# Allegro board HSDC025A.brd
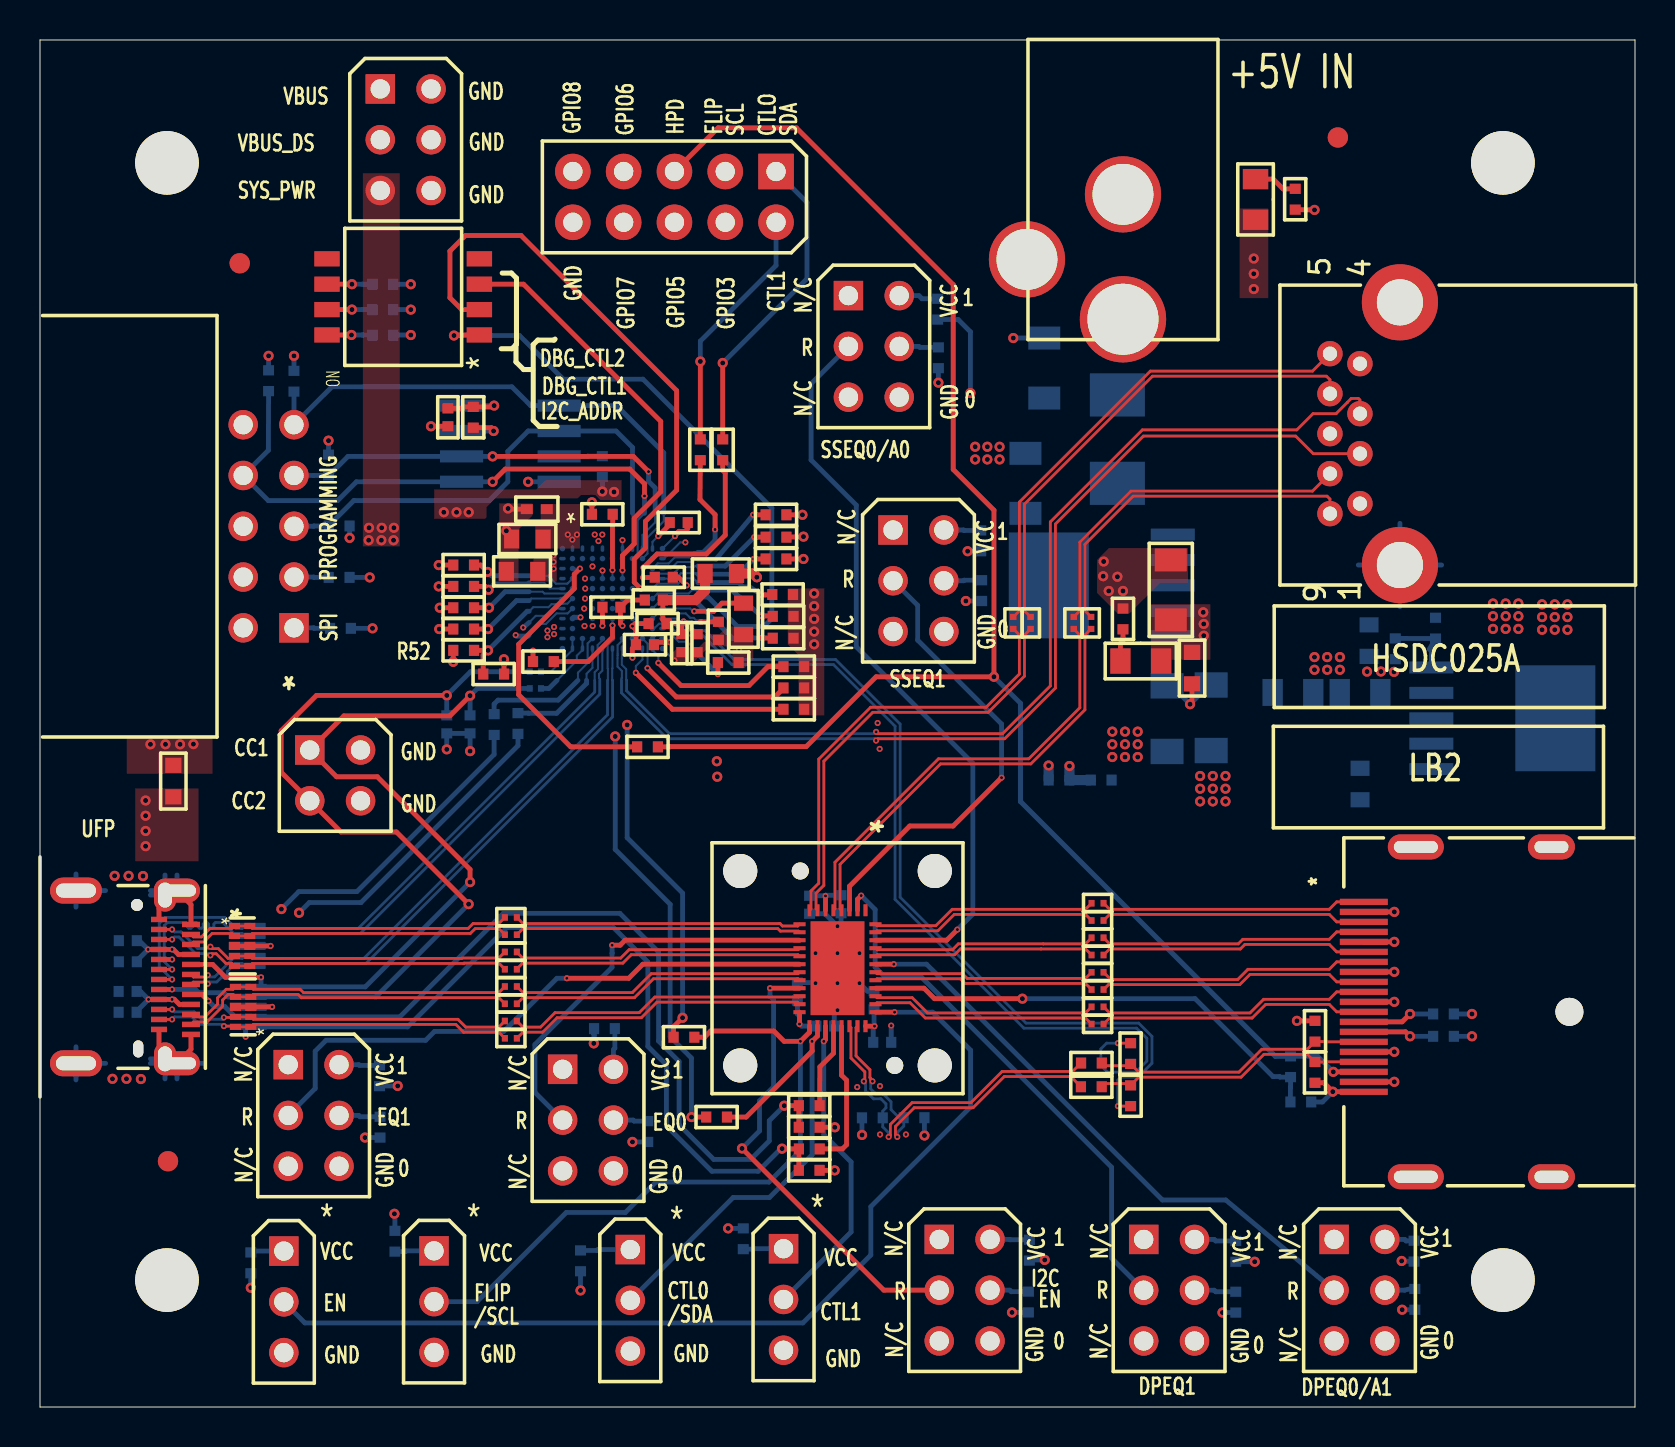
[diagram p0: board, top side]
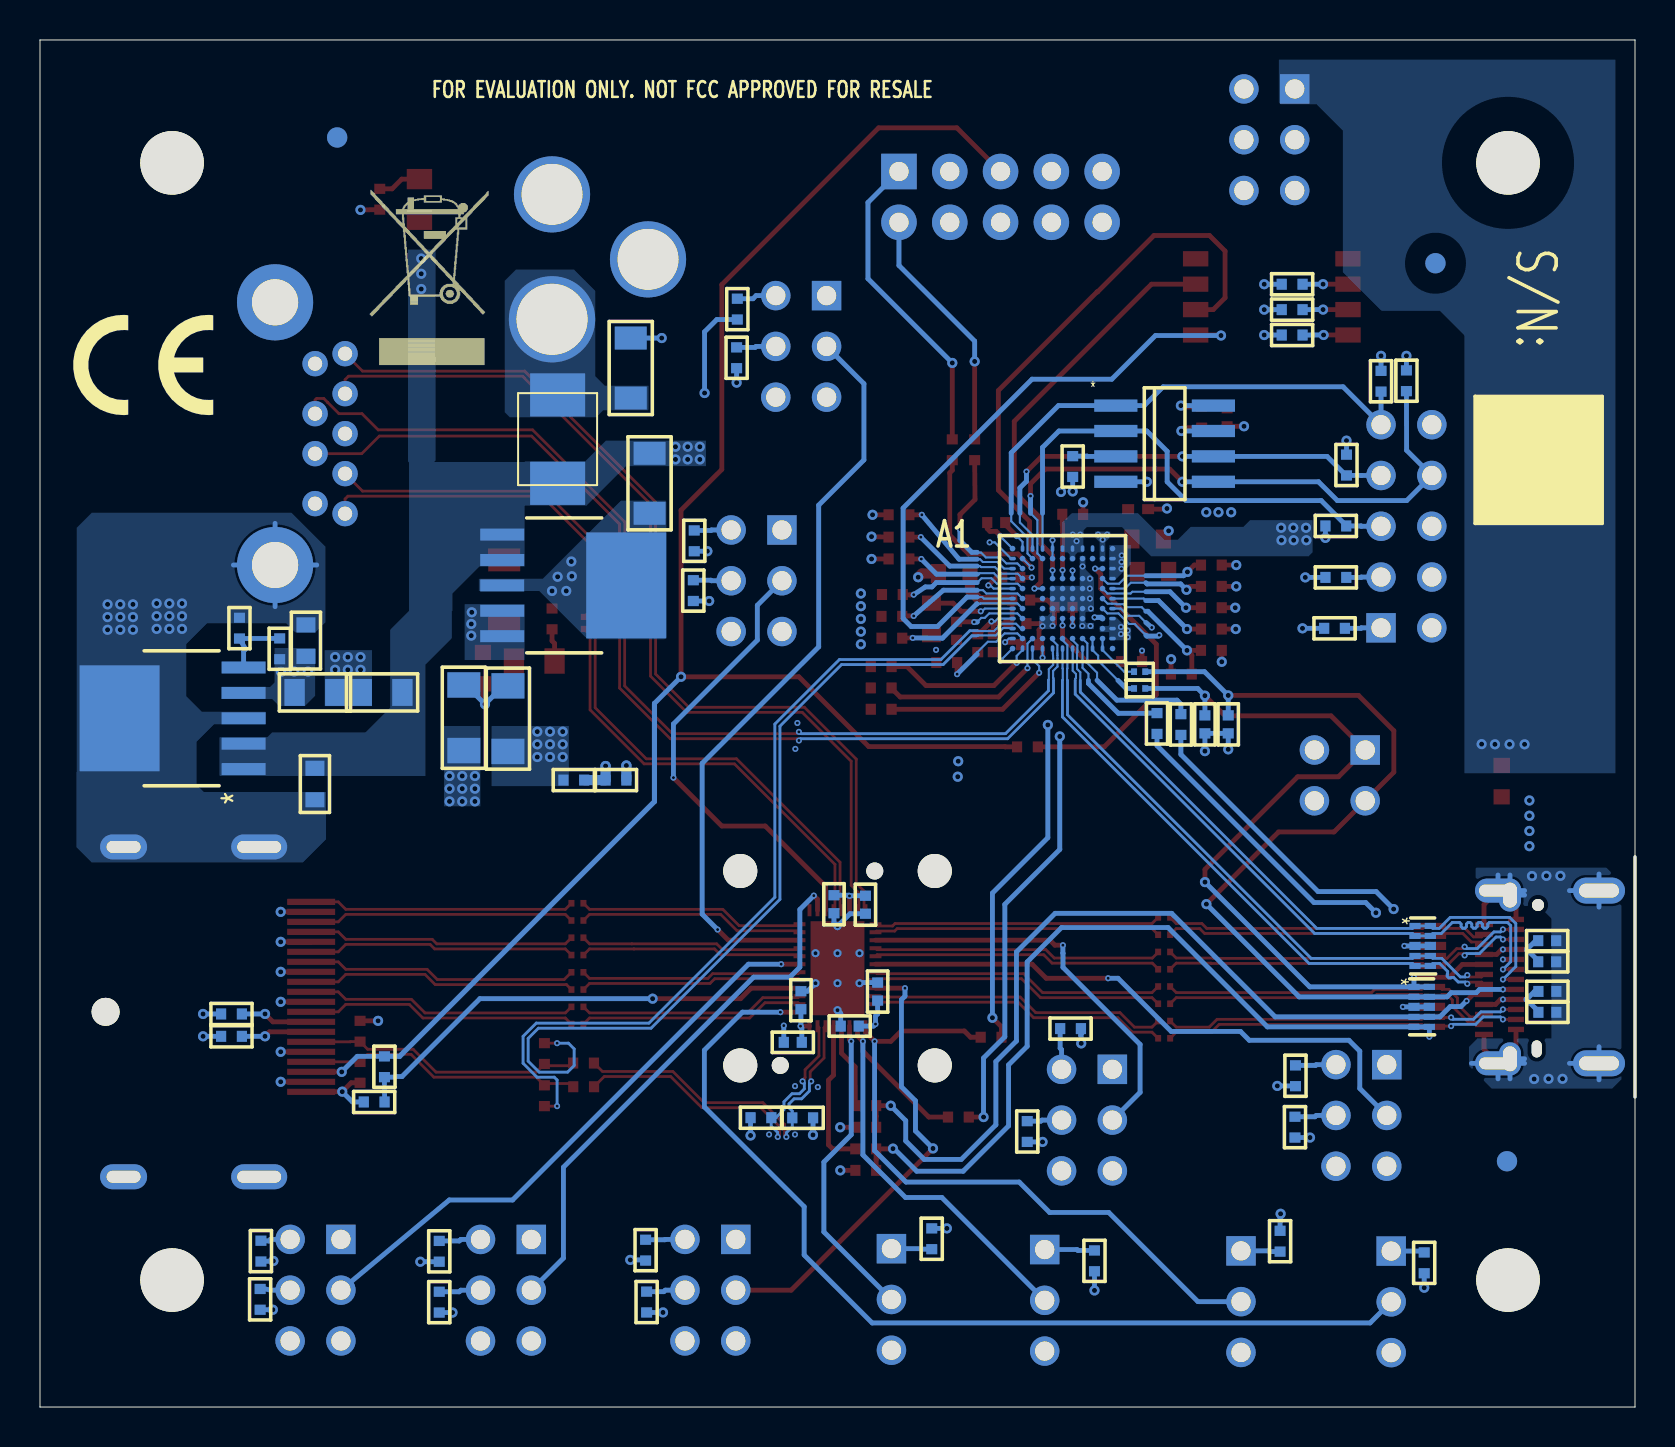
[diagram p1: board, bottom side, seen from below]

Outline 79.76 x 68.38 mm; copper layers: TOP, L2_GND, L3_PWR, L4_PWR, L5_GND, BOTTOM. Coordinates in mm from the lower left corner of the outline.
Outline path: 0,68.38 79.76,68.38 79.76,0 0,0 0,68.38

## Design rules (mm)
net group DIFFPAIR0: nets SSTXN SSTXP
net group DIFFPAIR1: nets SSRXN SSRXP
net group DIFFPAIR2: nets N73513 N73520
net group DIFFPAIR3: nets N53113 N53117
net group DIFFPAIR4: nets USB_N USB_P
net group DIFFPAIR5: nets RX1N RX1P
net group DIFFPAIR6: nets C_USB_BN C_USB_BP
net group DIFFPAIR7: nets TX2N TX2P
net group DIFFPAIR8: nets RX2N RX2P
net group DIFFPAIR9: nets C_USB_TN C_USB_TP
net group DIFFPAIR10: nets TX1N TX1P
net group DIFFPAIR11: nets DP0N DP0P
net group DIFFPAIR12: nets DP1N DP1P
net group DIFFPAIR13: nets DP2N DP2P
net group DIFFPAIR14: nets DP3N DP3P
net group DIFFPAIR15: nets AUXN AUXP
net group DIFFPAIR16: nets N53375 N53379
net group DIFFPAIR17: nets N53383 N53387
net group DIFFPAIR18: nets N53391 N53395
net group DIFFPAIR19: nets N53399 N53403
net group DIFFPAIR20: nets N62024 N62031
net group DIFFPAIR21: nets N52896 N52900
net group DIFFPAIR22: nets N16705873 N16705894
net group DIFFPAIR23: nets N16705898 N16705902
net group DIFFPAIR24: nets N52912 N52916
net group DIFFPAIR25: nets TPS_AUX_N TPS_AUX_P

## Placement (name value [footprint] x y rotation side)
C1  100nF  [C0201]  49.53 39.22 270 top
C2  470nF  [C0201]  51.69 39.22 90 top
C3  470nF  [C0201]  52.55 39.22 90 top
C4  220nF  [C0201]  23.55 24.49 0 top
C5  100nF  [C0201]  52.88 25.2 0 top
C6  220nF  [C0201]  23.55 23.62 0 top
C7  100nF  [C0201]  52.88 24.33 0 top
C8  470nF  [C0201]  23.55 22.76 0 top
C9  100nF  [C0201]  48.67 39.22 270 top
C10  100nF  [C0201]  52.88 23.47 0 top
C11  470nF  [C0201]  23.55 21.9 0 top
C12  100nF  [C0201]  52.88 22.61 0 top
C13  470nF  [C0201]  23.55 21.03 0 top
C14  100nF  [C0201]  52.88 21.74 0 top
C15  470nF  [C0201]  23.55 20.17 0 top
C16  100nF  [C0201]  52.88 20.88 0 top
C17  220nF  [C0201]  23.55 19.31 0 top
C18  100nF  [C0201]  52.88 20.02 0 top
C19  220nF  [C0201]  23.55 18.44 0 top
C20  100nF  [C0201]  52.88 19.15 0 top
C21  1uF  [C0402]  38.48 25.12 270 bottom
C22  1uF  [C0402]  41.71 20.35 90 bottom
C23  1uF  [C0402]  42.11 18.24 0 bottom
C24  100nF  [C0402]  40.06 25.15 270 bottom
C25  100nF  [C0402]  37.87 20.78 90 bottom
C26  10nF  [C0402]  39.27 19.05 0 bottom
C27  0.22uF  [C0402]  28.57 40.01 0 top
C28  330pF  [C0402]  21.51 34.15 270 bottom
C29  330pF  [C0402]  20.34 34.15 270 bottom
C30  10uF  [C0603]  35.18 39.42 270 top
C31  1uF  [C0402]  31.94 44.24 0 top
C32  1uF  [C0402]  30.25 38.13 180 top
C33  1uF  [C0402]  31.19 41.5 180 top
C34  1uF  [C0402]  33.92 38.82 270 top
C35  1uF  [C0402]  30.69 40.36 180 top
C36  1uF  [C0402]  32.09 38.21 270 top
C37  0.1uF  [C0402]  30.88 39.18 180 top
C38  0.1uF  [C0402]  32.87 38.2 270 top
C39  0.01uF  [C0402]  20.4 49.5 270 top
C40  22uF  [C1206]  49.28 46.2 270 bottom
C41  10uF  [C1206]  56.54 40.87 90 top
C42  10uF  [C1206]  50.22 51.97 90 bottom
C43  10uF  [C0603]  66.46 38.33 90 bottom
C44  10uF  [C0603]  66.01 31.16 270 bottom
C45  10nF  [C0402]  4.38 20.79 180 bottom
C46  10nF  [C0402]  4.38 19.74 180 bottom
C47  10nF  [C0402]  4.39 23.32 180 bottom
C48  10nF  [C0402]  4.39 22.27 180 bottom
C49  10uF  [C0603]  24.1 41.8 180 top
C50  10uF  [C0603]  34.04 41.69 0 top
C51  1uF 25V  [C0603]  24.37 43.42 180 top
D1  SCHOTTKY  [DO-214AA]  53.87 48.41 90 bottom
D2  LED Green  [0805]  55.04 37.31 180 top
D3  TPD1E10B06  [DPY0002AA]  24.84 44.91 180 top
D4  LED Green 0805  [0805]  60.78 60.4 90 top
FB1  26 @ 100MHZ  [0603]  57.61 36.96 90 top
FB2  26 @ 100MHZ  [0603]  6.67 31.31 90 top
J1  HDR3X1 M .1  [HDR_THVT_1X3_100_M]  19.7 7.81 0 top
J2  HDR3X1 M .1  [HDR_THVT_1X3_100_M]  29.52 7.88 0 top
J3  HDR3X1 M .1  [HDR_THVT_1X3_100_M]  37.18 7.92 0 top
J4  HDR3X1 M .1  [HDR_THVT_1X3_100_M]  12.19 7.8 0 top
J5  HDR3X2 .1X.1  [HDR_THVT_2X3_100_M]  17.02 65.93 0 top
J6  HDR2X2 M .1X.1  [HDR_THVT_2X2_100]  13.49 32.86 0 top
J7  Header 5x2 0.1" Shroud RA thru-hole  [HDR_THRT_2X5_100]  12.7 38.97 180 top
J8  2.1mm x 5.5mm  [PJ-202AH]  54.15 54.41 180 top
JMP1  HDR3X2 .1X.1  [HDR_THVT_2X3_100_M]  12.41 17.12 0 top
JMP2  HDR3X2 .1X.1  [HDR_THVT_2X3_100_M]  26.13 16.89 0 top
JMP3  HDR3X2 .1X.1  [HDR_THVT_2X3_100_M]  42.66 43.87 0 top
JMP4  HDR3X2 .1X.1  [HDR_THVT_2X3_100_M]  40.42 55.59 0 top
JMP5  HDR3X2 .1X.1  [HDR_THVT_2X3_100_M]  55.19 8.38 0 top
JMP6  HDR3X2 .1X.1  [HDR_THVT_2X3_100_M]  64.71 8.38 0 top
JMP7  HDR3X2 .1X.1  [HDR_THVT_2X3_100_M]  44.97 8.38 0 top
JMP8  Header 5x2  [HDR_THVT_2X5_100]  36.8 61.8 270 top
NOREF  -  []  79.76 0 90 top
NOREF#2  -  []  0 68.38 0 top
NOREF#3  -  []  0 0 0 top
NOREF#4  -  [unnamed#2]  6.35 6.35 0 top
NOREF#5  -  []  88.9 38.1 0 top
NOREF#6  -  [unnamed#2]  73.15 62.23 0 top
NOREF#7  -  [unnamed#2]  73.15 6.35 0 top
NOREF#8  -  [unnamed#2]  6.4 12.29 0 top
NOREF#9  -  [unnamed#2]  64.9 63.5 0 top
NOREF#10  -  []  -3.81 -69.85 0 top
NOREF#11  -  [unnamed#2]  9.99 57.21 0 top
NOREF#12  -  [unnamed#2]  6.35 62.23 0 top
NOREF#13  -  []  40.28 58.8 0 top
NOREF#14  -  []  60.26 57.7 180 bottom
NOREF#15  -  [unnamed#2]  64.9 63.5 180 bottom
NOREF#16  -  [unnamed#2]  6.4 12.29 180 bottom
NOREF#17  -  []  74.59 52.12 180 bottom
NOREF#18  -  []  7 32.26 180 bottom
NOREF#19  -  [unnamed#2]  9.98 57.21 180 bottom
NOREF#20  -  []  4.82 57.53 270 bottom
P1  JAE  DX07S024JJ2  [USB-C_SMRT_DX07S024JJ2]  4.85 21.51 270 top
P2  USB3 Type A Receptacle  [USB3_TYPEA]  64.5 48.69 90 top
P3  Display_Port_Connector_Source  [CON_DP_SD-47272-001]  76.48 19.77 90 top
R1  10k DNI  [R0402]  63.05 15.26 180 bottom
R2  0  [R0402]  62.53 17.02 90 bottom
R3  0 DNI  [R0402]  32.2 18.5 0 top
R4  100k DNI  [R0402]  63.75 16.74 90 top
R5  0 DNI  [R0402]  33.83 14.5 0 top
R6  0  [R0402]  52.57 16.02 0 top
R7  0  [R0402]  38.47 15.07 0 top
R8  0  [R0402]  52.58 17.21 0 top
R9  1M  [R0402]  70.18 19.66 0 bottom
R10  5M  [R0402]  70.18 18.54 0 bottom
R11  0  [R0402]  38.47 12.91 0 top
R12  1M DNI  [R0402]  41.62 14.47 180 bottom
R13  1M DNI  [R0402]  43.71 14.47 0 bottom
R14  100k DNI  [R0402]  63.75 18.8 90 top
R15  0 DNI  [R0402]  22.71 34.14 90 bottom
R16  0 DNI  [R0402]  23.9 34.19 90 bottom
R17  0 DNI  [R0402]  54.53 17.68 90 top
R18  0 DNI  [R0402]  54.53 15.57 270 top
R19  1K  [R0402]  16.98 16.57 270 bottom
R20  1K  [R0402]  28.22 18.93 180 bottom
R21  20K  [R0402]  17 14 270 bottom
R22  1K  [R0402]  17.75 8.29 90 bottom
R23  20K  [R0402]  30.39 13.78 270 bottom
R24  1K  [R0402]  47.04 43.32 270 bottom
R25  1K  [R0402]  44.89 54.91 270 bottom
R26  20K  [R0402]  47.09 40.84 270 bottom
R27  20K  [R0402]  44.92 52.48 270 bottom
R28  1K  [R0402]  27.03 7.31 270 bottom
R29  1K  [R0402]  59.79 7.79 270 bottom
R30  1K  [R0402]  68.71 7.8 270 bottom
R31  20K  [R0402]  59.79 5.25 270 bottom
R32  20K  [R0402]  68.75 5.38 270 bottom
R33  1K  [R0402]  35.17 8.42 90 bottom
R34  1K  [R0402]  49.47 7.85 270 bottom
R35  1K  [R0402]  10.54 7.21 270 bottom
R36  20K  [R0402]  49.42 5.25 270 bottom
R37  0  [R0201]  24.77 35.94 180 bottom
R38  0  [R0201]  24.77 36.78 180 bottom
R39  15k 0.1%  [R0402]  37.16 38.46 0 top
R40  0  [R0402]  30.38 33.02 180 top
R41  0  [R0402]  34.14 47.88 90 top
R42  0  [R0402]  21.18 39.98 0 top
R43  0  [R0402]  33.02 47.88 90 top
R44  0  [R0402]  21.18 42.11 180 top
R45  1M  [R0402]  37.69 37.03 180 top
R46  0 DNI  [R0402]  25.17 37.29 180 top
R47  1M  [R0402]  34.42 37.24 180 top
R48  1M  [R0402]  37.69 34.9 180 top
R49  1M  [R0402]  37.69 35.97 180 top
R50  1M  [R0402]  21.18 41.05 180 top
R51  1M  [R0402]  21.18 38.91 180 top
R52  100k DNI  [R0402]  21.18 37.85 180 top
R53  100k  [R0402]  37.13 40.64 180 top
R57  10k  [R0402]  36.8 44.63 180 top
R58  3.3k  [R0402]  36.8 43.51 180 top
R59  3.3k  [R0402]  36.8 42.42 180 top
R60  100k  [R0402]  37.16 39.55 180 top
R61  1K  [R0402]  28.12 44.65 180 top
R62  1K  [R0402]  17.14 56.16 0 bottom
R63  1K  [R0402]  17.14 54.89 0 bottom
R64  1K  [R0402]  17.14 53.62 0 bottom
R66  0  [R0402]  15.02 38.95 180 bottom
R67  3.3k  [R0402]  12.7 51.31 270 bottom
R68  3.3k  [R0402]  14.96 44.07 180 bottom
R70  0  [R0402]  14.96 41.5 180 bottom
R71  3.3k DNI  [R0402]  11.43 51.33 270 bottom
R72  3.3k  [R0402]  14.43 47.12 270 bottom
R73  3.3k  [R0402]  28.12 47.04 270 bottom
R74  3.3k  [R0402]  21.67 49.5 270 top
R75  0  [R1206]  58.56 34.48 90 bottom
R76  0  [R1206]  56.36 34.43 90 bottom
R77  330  [R0402]  54.15 39.42 90 top
R78  330  [R0402]  62.77 60.41 270 top
R79  0 DNI  [R0805]  66.01 35.74 180 bottom
R80  3.9K  [R0402]  67.77 37.92 90 bottom
R81  1.2K  [R0402]  69.78 38.96 90 bottom
R82  0 DNI  [R0805]  62.65 35.74 180 bottom
R83  2M  [R0402]  38.46 13.99 0 top
R84  2M  [R0402]  38.46 11.84 0 top
R85  0  [R0402]  53.06 31.36 180 bottom
R86  0 DNI  [R0402]  50.95 31.36 180 bottom
R87  100k  [R0402]  22.68 36.66 0 top
SW1  4-POS 50-MIL SMT  [SW_SMVT_DIP_4POS_8]  18.16 55.53 90 top
U1  TUSB1064  [SKT_IRONWOOD_C14861_QFN-40]  39.88 21.95 270 top
U2  TPD4E05U06  [DQA]  10.11 23.06 270 top
U3  TPD4E05U06  [DQA]  10.67 20.02 270 bottom
U4  TPD4E05U06  [DQA]  10.16 20.02 90 top
U5  TPD4E05U06  [DQA]  10.62 23.06 270 bottom
U6  TPS65986  [ZQZ_BGA_96]  28.63 40.44 180 bottom
U7  W25Q80  [SOIC_8_197X157_50]  23.52 48.18 180 bottom
U8  TPS7A4533  [DCQ_PDSO_6]  53.54 41.1 270 bottom
U9  TPS7A4501  [DCQ_PDSO_6]  72.67 34.45 90 bottom

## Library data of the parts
C1-C20 = cc0201
C21-C29 C31-C39 C45-C48 = cc0402
C30 C43 C44 C49-C51 = cc0603
C40-C42 = CAP NP
D1 = SCHOTTKY_2
D2 D4 = DIODE
D3 = TPD1E10B06
FB1 FB2 = FERRITE BEAD
J1-J4 = HDR3X1 M .1
J5 JMP1-JMP7 = HDR3X2 M .1X.1
J6 = HDR2X2 M .1X.1
J7 = CONN PCB 5x2-S
J8 = BNC_2
JMP8 = Header 5x2
P1 = TypeC_JAE_TopMNT_0
P2 = USB 3.0 Type A Receptacle
P3 = Display_Port_Connector_Source
R1-R36 R39-R53 R57-R64 R66-R68 R70-R74 R80 R81 R83-R87 = r0402
R37 R38 = r0201
R75 R76 = r1206
R77 R78 = R
R79 R82 = r0805
SW1 = SW DIP-4
U1 = TUSB1064
U2-U5 = TPD4E05U06
U6 = TPS65982_0
U7 = W25Q80SSI
U8 = TPS79633KTT_2
U9 = TPS7A4501

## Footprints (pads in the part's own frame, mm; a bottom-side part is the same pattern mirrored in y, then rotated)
0603
  rect 0.762x0.813 smd: 1(-0.787,0) 2(0.787,0)
0805
  rect 1.016x1.27 smd: 1(-1.016,0) 2(1.016,0)
C0201
  rect 0.3x0.33 smd: 1(-0.3,0) 2(0.3,0)
C0402
  rect 0.51x0.55 smd: 1(-0.45,0) 2(0.45,0)
C0603
  rect 0.76x0.95 smd: 1(-0.787,0) 2(0.787,0)
C1206
  rect 1.15x1.6 smd: 1(-1.5,0) 2(1.5,0)
CON_DP_SD-47272-001
  round 1.4 hole 1.4 unplated: (0,0)
  rect 0.31x2.4 smd: 1(5.5,10.28) 2(5,10.28) 3(4.5,10.28) 4(4,10.28) 5(3.5,10.28) 6(3,10.28) 7(2.5,10.28) 8(2,10.28) 9(1.5,10.28) 10(1,10.28) 11(0.5,10.28) 12(0,10.28) 13(-0.5,10.28) 14(-1,10.28) 15(-1.5,10.28) 16(-2,10.28) 17(-2.5,10.28) 18(-3,10.28) 19(-3.5,10.28) 20(-4,10.28)
  oval 1.25x2.8 hole 0.6x2.2: 21(-8.25,7.68) 24(8.25,7.68)
  oval 1.25x2.35 hole 0.6x1.7: 22(-8.25,0.9) 23(8.25,0.9)
DCQ_PDSO_6
  rect 0.6x2.2 smd: 1(-2.54,-3.1) 2(-1.27,-3.1) 3(0,-3.1) 4(1.27,-3.1) 5(2.54,-3.1)
  rect 5.3x4 smd: 6(0,3.1)
DO-214AA
  rect 2.16x2.75 smd: 1(-2.21,0) 2(2.21,0)
DPY0002AA
  rect 0.6x0.5 smd: 1(-0.5,0) 2(0.5,0)
DQA
  rect 0.305x0.559 smd: 1(-1,-0.385) 2(-0.5,-0.385) 4(0.5,-0.385) 5(1,-0.385) 6(1,0.385) 7(0.5,0.385) 9(-0.5,0.385) 10(-1,0.385)
  rect 0.406x0.559 smd: 3(0,-0.385) 8(0,0.385)
HDR_THRT_2X5_100
  rect 1.473x1.473 hole 0.965: 1(0,0)
  round 1.473 hole 0.965: 2(2.54,0) 3(0,-2.54) 4(2.54,-2.54) 5(0,-5.08) 6(2.54,-5.08) 7(0,-7.62) 8(2.54,-7.62) 9(0,-10.16) 10(2.54,-10.16)
HDR_THVT_1X3_100_M
  rect 1.473x1.473 hole 0.965: 1(0,0)
  round 1.473 hole 0.965: 2(0,-2.54) 3(0,-5.08)
HDR_THVT_2X2_100
  rect 1.473x1.473 hole 0.965: 1(0,0)
  round 1.473 hole 0.965: 2(2.54,0) 3(0,-2.54) 4(2.54,-2.54)
HDR_THVT_2X3_100_M
  rect 1.473x1.473 hole 0.965: 1(0,0)
  round 1.473 hole 0.965: 2(2.54,0) 3(0,-2.54) 4(2.54,-2.54) 5(0,-5.08) 6(2.54,-5.08)
HDR_THVT_2X5_100
  rect 1.778x1.778 hole 0.965: 1(0,0)
  round 1.778 hole 0.965: 2(2.54,0) 3(0,-2.54) 4(2.54,-2.54) 5(0,-5.08) 6(2.54,-5.08) 7(0,-7.62) 8(2.54,-7.62) 9(0,-10.16) 10(2.54,-10.16)
PJ-202AH
  round 4.318 hole 3.556: 1(0,0)
  round 3.81 hole 3.048: 2(4.801,-2.997) 3(0,-6.248)
R0201
  rect 0.3x0.33 smd: 1(-0.285,0) 2(0.275,0)
R0402
  rect 0.51x0.55 smd: 1(-0.52,0) 2(0.52,0)
R0805
  rect 1.02x1.35 smd: 1(-1.016,0) 2(1.016,0)
R1206
  rect 1.27x1.65 smd: 1(-1.64,0) 2(1.64,0)
SKT_IRONWOOD_C14861_QFN-40
  round 1.702 hole 1.702 unplated: (-4.863,4.863) (-4.863,-4.863) (4.863,4.863) (4.863,-4.863)
  round 0.85 hole 0.85 unplated: (-4.863,-1.863) (4.863,2.863)
  rect 0.6x0.2 smd: 1(-2.9,1.4) 2(-2.9,1) 3(-2.9,0.6) 4(-2.9,0.2) 5(-2.9,-0.2) 6(-2.9,-0.6) 7(-2.9,-1) 8(-2.9,-1.4) 21(2.9,-1.4) 22(2.9,-1) 23(2.9,-0.6) 24(2.9,-0.2) 25(2.9,0.2) 26(2.9,0.6) 27(2.9,1) 28(2.9,1.4)
  rect 0.2x0.6 smd: 9(-2.2,-1.9) 10(-1.8,-1.9) 11(-1.4,-1.9) 12(-1,-1.9) 13(-0.6,-1.9) 14(-0.2,-1.9) 15(0.2,-1.9) 16(0.6,-1.9) 17(1,-1.9) 18(1.4,-1.9) 19(1.8,-1.9) 20(2.2,-1.9) 29(2.2,1.9) 30(1.8,1.9) 31(1.4,1.9) 32(1,1.9) 33(0.6,1.9) 34(0.2,1.9) 35(-0.2,1.9) 36(-0.6,1.9) 37(-1,1.9) 38(-1.4,1.9) 39(-1.8,1.9) 40(-2.2,1.9)
  rect 4.699x2.692 smd: 41(0,0)
SOIC_8_197X157_50
  rect 2.159x0.61 smd: 1(-2.44,1.905) 2(-2.44,0.635) 3(-2.44,-0.635) 4(-2.44,-1.905) 5(2.44,-1.905) 6(2.44,-0.635) 7(2.44,0.635) 8(2.44,1.905)
SW_SMVT_DIP_4POS_8
  rect 0.762x1.27 smd: 1(-1.905,-3.81) 2(-0.635,-3.81) 3(0.635,-3.81) 4(1.905,-3.81) 5(1.905,3.81) 6(0.635,3.81) 7(-0.635,3.81) 8(-1.905,3.81)
unnamed#2
  round 3.175 hole 3.175 unplated: (0,0)
USB3_TYPEA
  round 1.27 hole 0.711: 1(-3.5,-1.5) 2(-1,-1.5) 3(1,-1.5) 4(3.5,-1.5) 5(4,0) 6(2,0) 7(0,0) 8(-2,0) 9(-4,0)
  round 3.81 hole 2.311: 10(-6.57,-3.5) 11(6.57,-3.5)
USB-C_SMRT_DX07S024JJ2
  round 0.6 hole 0.6 unplated: (-3.6,0)
  oval 0.85x0.5 hole 0.85x0.5 unplated: (3.6,0.065)
  oval 1.65x1.1 hole 1.25x0.7: 1(-4.095,1.4) 5(4.095,1.4)
  oval 1.2x2.3 hole 0.6x1.9: 2(-4.32,2) 6(4.32,2)
  oval 1.3x2.6 hole 0.7x2: 3(-4.32,-3.05) 4(4.32,-3.05)
  rect 0.27x0.9 smd: A1(-2.625,2.7) A2(-2.125,2.7) A3(-1.625,2.7) A4(-1.125,2.7) A5(-0.625,2.7) A6(-0.125,2.7) A7(0.375,2.7) A8(0.875,2.7) A9(1.375,2.7) A10(1.875,2.7) A11(2.375,2.7) A12(2.875,2.7)
  rect 0.27x0.8 smd: B1(2.625,1.1) B2(2.125,1.1) B3(1.625,1.1) B4(1.125,1.1) B5(0.625,1.1) B6(0.125,1.1) B7(-0.375,1.1) B8(-0.875,1.1) B9(-1.375,1.1) B10(-1.875,1.1) B11(-2.375,1.1) B12(-2.875,1.1)
ZQZ_BGA_96
  round 0.28 smd: A1(-2.5,2.5) A11(2.5,2.5) B2(-2,2) B3(-1.5,2) B4(-1,2) B5(-0.5,2) B6(0,2) B7(0.5,2) B8(1,2) B9(1.5,2) B10(2,2) C2(-2,1.5) C10(2,1.5) D2(-2,1) D5(-0.5,1) D6(0,1) D7(0.5,1) D8(1,1) D10(2,1) E2(-2,0.5) E4(-1,0.5) E5(-0.5,0.5) E6(0,0.5) E7(0.5,0.5) E8(1,0.5) E10(2,0.5) F2(-2,0) F4(-1,0) F5(-0.5,0) F6(0,0) F7(0.5,0) F8(1,0) F10(2,0) G2(-2,-0.5) G4(-1,-0.5) G5(-0.5,-0.5) G6(0,-0.5) G7(0.5,-0.5) G8(1,-0.5) G10(2,-0.5) H2(-2,-1) H4(-1,-1) H5(-0.5,-1) H6(0,-1) H7(0.5,-1) H8(1,-1) H10(2,-1) J2(-2,-1.5) J10(2,-1.5) K2(-2,-2) K3(-1.5,-2) K4(-1,-2) K5(-0.5,-2) K6(0,-2) K7(0.5,-2) K8(1,-2) K9(1.5,-2) K10(2,-2) L1(-2.5,-2.5) L11(2.5,-2.5)
  oval 0.18x0.33 smd: A2(-2,2.5) A3(-1.5,2.5) A4(-1,2.5) A5(-0.5,2.5) A6(0,2.5) A7(0.5,2.5) A8(1,2.5) A9(1.5,2.5) A10(2,2.5) L2(-2,-2.5) L3(-1.5,-2.5) L4(-1,-2.5) L5(-0.5,-2.5) L6(0,-2.5) L7(0.5,-2.5) L8(1,-2.5) L9(1.5,-2.5) L10(2,-2.5)
  oval 0.33x0.18 smd: B1(-2.5,2) B11(2.5,2) C1(-2.5,1.5) C11(2.5,1.5) D1(-2.5,1) D11(2.5,1) E1(-2.5,0.5) E11(2.5,0.5) F1(-2.5,0) F11(2.5,0) G1(-2.5,-0.5) G11(2.5,-0.5) H1(-2.5,-1) H11(2.5,-1) J1(-2.5,-1.5) J11(2.5,-1.5) K1(-2.5,-2) K11(2.5,-2)

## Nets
GND: C21.2 C22.2 C23.2 C24.2 C25.2 C26.2 C27.2 C28.2 C29.2 C30.2 C31.2 C32.2 C33.2 C34.2 C35.2 C36.2 C37.2 C38.2 C39.2 C40.2 C41.2 C42.2 C43.2 C44.2 C45.2 C46.2 C47.2 C48.2 C49.2 C50.2 C51.2 D3.2 J1.3 J2.3 J3.3 J4.3 J5.2 J5.4 J5.6 J6.2 J6.4 J7.2(6) J7.10 J8.2(S) J8.3(SW) JMP1.6 JMP2.6 JMP3.6 JMP4.6 JMP5.6 JMP6.6 JMP7.6 JMP8.10 P1.1(CHASSIS#1) P1.2(CHASSIS#2) P1.3(CHASSIS#3) P1.4(CHASSIS#4) P1.5(CHASSIS#5) P1.6(CHASSIS#6) P1.A1(GND#A1) P1.A12(GND#A12) P1.B1(GND#B1) P1.B12(GND#B12) P2.4(GND) P2.7(GND_DRAIN) P2.10(SHIELD1) P2.11(SHIELD2) P3.2(GND1) P3.5(GND2) P3.8(GND3) P3.11(GND4) P3.16(GND6) P3.19(RTN) P3.21(GND7) P3.22(GND8) P3.23(GND9) P3.24(GND10) R9.2 R10.2 R13.2 R14.2 R21.2 R23.2 R26.2 R27.2 R31.2 R32.2 R36.2 R39.2 R45.1 R47.1 R48.1 R49.1 R50.2 R51.2 R53.1 R60.1 R61.2 R62.2 R63.2 R64.2 R77.2 R78.2 R81.2 R83.2 R84.2 U1.41(PAD/GND) U2.3(GND#3) U2.8(GND#8) U3.3(GND#3) U3.8(GND#8) U4.3(GND#3) U4.8(GND#8) U5.3(GND#3) U5.8(GND#8) U6.A1(GND#A1) U6.A5(GND#A5) U6.B5(GND#B5) U6.B8(GND#B8) U6.D8(GND#D8) U6.E5(GND#E5) U6.E6(GND#E6) U6.E7(GND#E7) U6.E8(GND#E8) U6.F5(GND#F5) U6.F6(GND#F6) U6.F7(GND#F7) U6.F8(GND#F8) U6.G5(GND#G5) U6.G6(GND#G6) U6.G7(GND#G7) U6.G8(GND#G8) U6.H4(GND#H4) U6.H5(GND#H5) U6.H8(GND#H8) U6.L1(GND#L1) U6.L4(GND#L4) U7.4(GND) U8.3(GND#3) U8.6(GND#6) U9.3(GND#3) U9.6(GND#6)
VBUS: C51.1 D3.1 FB2.2 J5.1 R79.2 R82.1 U6.A10(SENSEN) U6.B10(SENSEP) U6.H11(VBUS1) U6.J10(VBUS2) U6.J11(VBUS3) U6.K11(VBUS4)
VBUS_DS: C43.1 C49.1 J5.3 P2.1(VBUS) R79.1 R80.1 U6.A11(PP_5V0_2) U6.B11(PP_5V0_1) U6.C11(PP_5V0_3) U6.D11(PP_5V0_4) U6.H10(PP_CABLE) U9.4(OUT)
VDDIO: R85.2 R86.1 U6.B1(VDDIO)
3P3VCC: C41.1 D2.1(A) FB1.2 P3.20(DP_PWR) R1.1 R4.1 R12.2 U8.4(OUT) U8.5(SENSE)
1064_VCC: C21.1 C22.1 C23.1 C24.1 C25.1 C26.1 R19.2 R20.2 R22.2 R24.2 R25.2 R28.2 R29.2 R30.2 R33.2 R34.2 R35.2 R75.1 U1.6(VCC#6) U1.20(VCC#20) U1.28(VCC#28)
AUXN: P3.17(AUX_N) R4.2 R6.2 R18.1
AUXP: P3.15(AUX_P) R8.2 R14.1 R17.1
C_USB_BN: P1.B7(DN2) U5.2(D1-) U5.9(NC9) U6.L7(C_USB_BN)
C_USB_BP: P1.B6(DP2) U5.1(D1+) U5.10(NC10) U6.K7(C_USB_BP)
C_USB_TN: P1.A7(DN1) U5.5(D2-) U5.6(NC6) U6.L6(C_USB_TN)
C_USB_TP: P1.A6(DP1) U5.4(D2+) U5.7(NC7) U6.K6(C_USB_TP)
CC1: C28.1 J6.1 P1.A5(CC1) R37.2 U3.1(D1+) U3.10(NC10)
CC2: C29.1 J6.3 P1.B5(CC2) R38.2 U3.2(D1-) U3.9(NC9)
CONFIG1: P3.13(CAD) R9.1
CONFIG2: P3.14(GND5) R10.1
CTL0/SDA: J2.2 JMP8.1 R5.2 R41.2 U1.22(CTL0/SDA)
CTL1: J3.2 JMP8.2 R43.2 U1.23(CTL1)
DBG_CTL1: SW1.2 U6.E4(DBG_CTL1)
DBG_CTL2: SW1.3 U6.D5(DBG_CTL2)
DP0N: C7.2 P3.3(ML_0N)
DP0P: C5.2 P3.1(ML_0P)
DP1N: C12.2 P3.6(ML_1N)
DP1P: C10.2 P3.4(ML_1P)
DP2N: C16.2 P3.9(ML_2N)
DP2P: C14.2 P3.7(ML_2P)
DP3N: C20.2 P3.12(ML_3N)
DP3P: C18.2 P3.10(ML_3P)
DPEQ0/A1: JMP6.3 U1.35(DPEQ0/A1)
DPEQ1: JMP5.3 U1.2(DPEQ1)
EN: J4.2 U1.29(EN)
EQ0: JMP2.3 U1.11(EQ0)
EQ1: JMP1.3 U1.14(EQ1)
FLIP/SCL: J1.2 JMP8.3 R3.2 R44.2 U1.21(FLIP/SCL)
GPIO3: JMP8.4 U6.G11(GPIO3)
GPIO5: JMP8.6 R42.1
GPIO6: JMP8.7 U6.G10(GPIO6)
GPIO7: JMP8.8 U6.D7(GPIO7)
GPIO8: JMP8.9 R46.2
HPD: JMP8.5 P3.18(HPD) R2.2 R40.1
HPDIN: R1.2 R2.1 U1.32(HPDIN)
I2C_ADDR: SW1.1 U6.F1(I2C_ADDR)
I2C_EN: JMP7.3 U1.17(I2C_EN)
I2C_IRQ1Z: R57.2 U6.C1(I2C_IRQ1Z)
I2C_SCL: R3.1 R58.2 R66.1 U6.D2(I2C_SCL1)
I2C_SDA: R5.1 R59.2 R70.1 U6.D1(I2C_SDA1)
LCO_1P8VA: C32.1 U6.K1(LDO_1V8A)
LCO_1P8VD: C31.1 R87.2 U6.A2(LDO_1V8D)
LDO_3P3: C30.1 C39.1 R52.2 R57.1 R58.1 R59.1 R67.1 R68.1 R71.1 R72.1 R73.2 R74.1 R86.2 U6.G1(LDO_3V3) U7.8(VCC)
LDO_BMC: C33.1 U6.E1(LDO_BMC)
RX1N: C11.1 P1.B10(SSRXN1) U2.5(D2-) U2.6(NC6)
RX1P: C8.1 P1.B11(SSRXP1) U2.4(D2+) U2.7(NC7)
RX2N: C13.1 P1.A10(SSRXN2) U4.5(D2-) U4.6(NC6)
RX2P: C15.1 P1.A11(SSRXP2) U4.4(D2+) U4.7(NC7)
SBU1: P1.A8(SBU1) R7.1 R15.1 R83.1 U3.4(D2+) U3.7(NC7)
SBU2: P1.B8(SBU2) R11.1 R16.1 R84.1 U3.5(D2-) U3.6(NC6)
SPI_CLK: J7.7(4) R72.2 U6.A3(SPI_CLK) U7.6(CLK)
SPI_HOLD#: R74.2 U7.7(/HOLD)
SPI_MISO: J7.5(3) R68.2 U6.A4(SPI_MISO) U7.2(DO)
SPI_MOSI: J7.8(9) R71.2 U6.B4(SPI_MOSI) U7.5(DI)
SPI_SSZ: J7.9(5) R67.2 U6.B3(SPI_SSZ) U7.1(/CS)
SPI_WP#: R73.1 U7.3(/WP)
SSEQ0/A0: JMP4.3 U1.38(SSEQ0/A0)
SSEQ1: JMP3.3 U1.3(SSEQ1)
SSRXN: C2.2 P2.8(SS_TX_N)
SSRXP: C3.2 P2.9(SS_TX_P)
SSTXN: C9.1 P2.5(SS_RX_N)
SSTXP: C1.1 P2.6(SS_RX_P)
SYS_PWR: C40.1 C44.1 D1.1(K) D4.1(A) J5.5 R82.2 U6.A6(PP_HV1) U6.A7(PP_HV2) U6.A8(PP_HV3) U6.B7(PP_HV4) U8.1(SHDN/) U8.2(IN) U9.1(SHDN/) U9.2(IN)
TPS65986_3P3V: C35.1 C36.1 C37.1 C38.1 C50.1 R76.1 R85.1 U6.H1(VIN_3V3)
TPS_AUX_N: R18.2 U6.J2(AUX_N)
TPS_AUX_P: R17.2 U6.J1(AUX_P)
TPS_SBU1: R15.2 U6.K8(C_SBU1)
TPS_SBU2: R16.2 U6.L8(C_SBU2)
TX1N: C6.1 P1.A3(SSTXN1) U2.2(D1-) U2.9(NC9)
TX1P: C4.1 P1.A2(SSTXP1) U2.1(D1+) U2.10(NC10)
TX2N: C17.1 P1.B3(SSTXN2) U4.2(D1-) U4.9(NC9)
TX2P: C19.1 P1.B2(SSTXP2) U4.1(D1+) U4.10(NC10)
USB_N: P2.2(USB2_DM) U6.K5(USB_RP_N)
USB_P: P2.3(USB2_DP) U6.L5(USB_RP_P)
VOUT_3P3: C34.1 U6.H2(VOUT_3V3)
N51428: C45.1 C46.1 C47.1 C48.1 FB2.1 P1.A4(VBUS#A4) P1.A9(VBUS#A9) P1.B4(VBUS#B4) P1.B9(VBUS#B9)
N52896: C4.2 U1.9(TX1P)
N52900: C6.2 U1.10(TX1N)
N52912: C17.2 U1.18(TX2N)
N52916: C19.2 U1.19(TX2P)
N53113: C2.1 U1.5(SSRXN)
N53117: C3.1 U1.4(SSRXP)
N53375: C5.1 U1.40(DP0P)
N53379: C7.1 U1.39(DP0N)
N53383: C10.1 U1.37(DP1P)
N53387: C12.1 U1.36(DP1N)
N53391: C14.1 U1.34(DP2P)
N53395: C16.1 U1.33(DP2N)
N53399: C18.1 U1.31(DP3P)
N53403: C20.1 U1.30(DP3N)
N54909: R37.1 U6.K9(RPD_G1) U6.L9(C_CC1)
N54981: R38.1 U6.K10(RPD_G2) U6.L10(C_CC2)
N60753: J1.1 R22.1
N61165: J2.1 R28.1
N61173: JMP3.4 R26.1
N61517: J3.1 R33.1
N61661: J4.1 R35.1
N62024: R6.1 R13.1 U1.27(AUXN)
N62031: R8.1 R12.1 U1.26(AUXP)
N62627: R11.2 U1.25(SBU2)
N62636: R7.2 U1.24(SBU1)
N63203: R41.1 U6.B2(GPIO0)
N63233: R43.1 U6.C2(GPIO1)
N63241: R44.1 U6.D10(GPIO2)
N63249: R40.2 U6.C10(GPIO4)
N73513: C1.2 U1.7(SSTXP)
N73520: C9.2 U1.8(SSTXN)
N75829: R42.2 U6.E10(GPIO5)
N78382: J7.1 R66.2
N78490: J7.3(2) R70.2
N79273: R49.2 U6.K3(DEBUG4)
N79277: R48.2 U6.L3(DEBUG3)
N79281: R47.2 U6.K2(DEBUG2)
N79285: R45.2 U6.L2(DEBUG1)
N80574: R51.1 U6.F11(RESETZ)
N80581: R50.1 U6.E11(MRESET)
N81425: R39.1 U6.G2(R_OSC)
N85567: R53.2 U6.E2(UART_TX)
N85571: R60.2 U6.F2(UART_RX)
N88590: R52.1 R87.1 U6.F10(BUSPOWERZ)
N89051: R62.1 SW1.6
N89058: R63.1 SW1.7
N89065: R64.1 SW1.8
N92164: R61.1 U6.D6(HRESET)
N95070: C27.1 U6.H7(SS)
N98885: D2.2(K) R77.1
N16697259: C42.1 D1.2(A) J8.1(T)
N16698171: FB1.1 R75.2 R76.2
N16698282: R46.1 U6.H6(GPIO8)
N16700173: D4.2(K) R78.1
N16705873: C8.2 U1.12(RX1P)
N16705894: C11.2 U1.13(RX1N)
N16705898: C13.2 U1.15(RX2N)
N16705902: C15.2 U1.16(RX2P)
N16750118: R80.2 R81.1 U9.5(ADJ)
N16816893: JMP1.2 R19.1
N16816902: JMP1.4 R21.1
N16816999: JMP3.2 R24.1
N16817208: JMP5.2 R29.1
N16817217: JMP5.4 R31.1
N16817279: JMP7.2 R34.1
N16817288: JMP7.4 R36.1
N16817349: JMP6.2 R30.1
N16817418: JMP6.4 R32.1
N16817489: JMP4.4 R27.1
N16817492: JMP4.2 R25.1
N16817504: JMP2.2 R20.1
N16817513: JMP2.4 R23.1

Pads without a net: J7 4 6; JMP1 1 5; JMP2 1 5; JMP3 1 5; JMP4 1 5; JMP5 1 5; JMP6 1 5; JMP7 1 5; SW1 4 5; U1 1; U6 A9 B6 B9 F4 G4 K4 L11

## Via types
v1: diameter 0.508, hole 0.254, TOP to BOTTOM, 190 vias
v2: diameter 0.305, hole 0.152, TOP to BOTTOM, 112 vias
v3: diameter 0.406, hole 0.203, TOP to BOTTOM, 8 vias

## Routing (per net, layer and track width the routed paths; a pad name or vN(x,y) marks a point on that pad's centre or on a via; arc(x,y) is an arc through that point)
GND: length 304.9
  TOP w0.241: P3.19 v1(67.72,16.27) ; U4.8 U4.3 v2(11.61,20.02) ; C39.2 v1(19.55,49.05) ; P1.A12 7.55,17.89 P1.6 ; P1.B12 5.95,24.93 P1.2 7.55,25.13 P1.A1 ; P1.5 5.95,17.72 P1.B1 ; C31.2 32.39,43.93 32.25,43.8 31.95,43.8 ; R83.2 v1(39.74,13.99) ; U2.3 U2.8 v2(11.53,23.06) ; P3.16 v1(67.72,17.77) ; v2(30.16,41.49) 30.73,41.49 C33.2 ; C35.2 29.38,40.36 C27.2 29.03,39.17 v2(29.13,39.07) ; P3.2 v1(67.72,24.77) ; P3.8 v1(67.72,21.77) ; D3.2 23.44,44.91 v1(23.4,44.94) ; R51.2 v1(19.96,38.91) ; R78.2 v1(63.73,59.88) ; R84.2 v1(39.74,11.84) ; C37.2 29.75,39.18 v2(29.63,39.06) 29.8,38.88 C32.2 29.8,38.13 29.62,37.95 29.62,37.49 v2(29.63,37.48) ; R50.2 v1(19.94,41.05) ; R14.2 v1(62.85,19.32) ; R61.2 v1(27.6,45.25) ; P3.5 v1(67.72,23.27) ; P3.11 v1(67.72,20.27)
  TOP w0.254: v2(31.75,43.56) 31.75,43.6 31.95,43.8
  TOP w0.508: v1(35.84,41.51) 35.66,41.69 C50.2
  L2_GND w0.241: J7.10 10.16,50.05 ; J7.10 10.16,48.22 ; J7.10 11.07,49.13 ; J7.10 9.25,49.13 ; P1.2 8.18,25.83 ; P1.2 6.85,26.61 ; P1.2 5.52,25.83 ; P2.11 70.08,55.26 ; P2.11 68,57.34 ; P2.11 65.92,55.26 ; P2.11 68,53.17 ; 15.12,32.86 J6.2 ; J6.2 16.03,31.95 ; J6.2 16.03,33.78 ; J6.2 16.94,32.86 ; 15.12,30.32 J6.4 ; J6.4 16.94,30.32 ; J6.4 16.03,29.41 ; J6.4 16.03,31.24 ; 26.64,58.19 JMP8.10 ; JMP8.10 27.71,59.26 ; JMP8.10 26.64,60.33 ; JMP8.10 25.58,59.26 ; P2.7 64.5,49.5 ; P2.7 64.5,47.87 ; P2.7 63.69,48.69 ; P2.7 65.31,48.69 ; 42.05,50.51 JMP4.6 ; JMP4.6 43.88,50.51 ; JMP4.6 42.96,49.6 ; JMP4.6 42.96,51.43 ; JMP6.6 68.16,3.3 ; JMP6.6 67.25,4.22 ; JMP6.6 66.33,3.3 ; JMP6.6 67.25,2.39 ; 29.52,1.88 J2.3 ; J2.3 29.52,3.71 ; J2.3 30.43,2.8 ; J2.3 28.6,2.8 ; P1.1 6.25,26.61 ; P1.1 6.25,24.6 ; P1.1 5.52,25.61 ; P1.3 3.28,25.83 ; P1.3 1.8,25 ; P1.3 1.8,26.66 ; P3.21 68.8,12.32 ; P3.21 68.8,10.71 ; P3.21 70.37,11.52 ; P3.21 67.22,11.52 ; JMP7.6 48.42,3.3 ; JMP7.6 47.51,2.39 ; JMP7.6 47.51,4.22 ; JMP7.6 46.59,3.3 ; JMP3.6 45.2,39.7 ; JMP3.6 46.11,38.79 ; JMP3.6 44.28,38.79 ; JMP3.6 45.2,37.87 ; P2.10 70.08,42.12 ; P2.10 65.92,42.12 ; P2.10 68,40.03 ; P2.10 68,44.2 ; 10.16,38.06 J7.2 ; J7.2 11.07,38.97 ; J7.2 10.16,39.89 ; J7.2 9.25,38.97 ; 75.58,10.71 P3.22 ; P3.22 75.58,12.32 ; P3.22 74.22,11.52 ; P3.22 76.93,11.52 ; P1.4 1.8,18.02 ; P1.4 3.28,17.19 ; P1.4 1.8,16.36 ; JMP1.6 15.87,12.04 ; JMP1.6 14.04,12.04 ; JMP1.6 14.95,12.96 ; JMP1.6 14.95,11.13 ; P1.5 6.25,18.42 ; P1.5 5.52,17.42 ; P1.5 6.25,16.41 ; 37.18,1.92 J3.3 ; J3.3 37.18,3.75 ; J3.3 38.1,2.84 ; J3.3 36.27,2.84 ; 12.19,1.81 J4.3 ; J4.3 12.19,3.64 ; J4.3 11.28,2.72 ; J4.3 13.11,2.72 ; J1.3 19.7,3.65 ; J1.3 20.62,2.73 ; J1.3 18.79,2.73 ; J1.3 19.7,1.82 ; P1.6 8.18,17.19 ; P1.6 6.85,16.41 ; P1.6 5.52,17.19 ; P2.4 66.81,52.19 ; P2.4 66,53 ; P2.4 66,51.37 ; 56.81,3.3 JMP5.6 ; JMP5.6 58.64,3.3 ; JMP5.6 57.73,2.39 ; JMP5.6 57.73,4.22 ; 28.67,11.81 28.67,12.73 ; 28.67,11.81 29.59,11.81 ; 28.67,11.81 27.76,11.81 ; 28.67,11.81 28.67,10.9
  L5_GND w0.241: P1.5 6.25,18.42 ; P1.5 5.52,17.42 ; P1.5 6.25,16.41 ; 15.12,30.32 J6.4 ; J6.4 16.94,30.32 ; J6.4 16.03,29.41 ; J6.4 16.03,31.24 ; JMP7.6 48.42,3.3 ; JMP7.6 47.51,2.39 ; JMP7.6 47.51,4.22 ; JMP7.6 46.59,3.3 ; JMP3.6 46.11,38.79 ; JMP3.6 44.28,38.79 ; JMP3.6 45.2,39.7 ; JMP3.6 45.2,37.87 ; 42.05,50.51 JMP4.6 ; JMP4.6 42.96,51.43 ; JMP4.6 42.96,49.6 ; JMP4.6 43.88,50.51 ; 14.04,12.04 JMP1.6 ; JMP1.6 14.95,11.13 ; JMP1.6 15.87,12.04 ; JMP1.6 14.95,12.96 ; P2.11 70.08,55.26 ; P2.11 68,57.34 ; P2.11 65.92,55.26 ; P2.11 68,53.17 ; JMP8.10 26.64,60.33 ; JMP8.10 25.58,59.26 ; JMP8.10 27.71,59.26 ; JMP8.10 26.64,58.19 ; P3.21 68.8,12.32 ; P3.21 68.8,10.71 ; P3.21 70.37,11.52 ; P3.21 67.22,11.52 ; J2.3 29.52,3.71 ; J2.3 28.6,2.8 ; J2.3 29.52,1.88 ; J2.3 30.43,2.8 ; 64.5,47.87 P2.7 ; P2.7 65.31,48.69 ; P2.7 63.69,48.69 ; P2.7 64.5,49.5 ; P2.10 68,44.2 ; P2.10 65.92,42.12 ; P2.10 70.08,42.12 ; P2.10 68,40.03 ; 75.58,10.71 P3.22 ; P3.22 76.93,11.52 ; P3.22 75.58,12.32 ; P3.22 74.22,11.52 ; 12.19,1.81 J4.3 ; J4.3 12.19,3.64 ; J4.3 11.28,2.72 ; J4.3 13.11,2.72 ; 6.85,16.41 P1.6 ; P1.6 5.52,17.19 ; P1.6 8.18,17.19 ; 6.25,24.6 P1.1 ; P1.1 5.52,25.61 ; P1.1 6.25,26.61 ; 15.12,32.86 J6.2 ; J6.2 16.94,32.86 ; J6.2 16.03,33.78 ; J6.2 16.03,31.95 ; P2.4 66.81,52.19 ; P2.4 66,53 ; P2.4 66,51.37 ; JMP6.6 68.16,3.3 ; JMP6.6 67.25,2.39 ; JMP6.6 66.33,3.3 ; JMP6.6 67.25,4.22 ; 1.8,25 P1.3 ; P1.3 3.28,25.83 ; P1.3 1.8,26.66 ; J7.10 11.07,49.13 ; J7.10 10.16,50.05 ; J7.10 10.16,48.22 ; J7.10 9.25,49.13 ; P1.4 3.28,17.19 ; P1.4 1.8,16.36 ; P1.4 1.8,18.02 ; 10.16,38.06 J7.2 ; J7.2 9.25,38.97 ; J7.2 11.07,38.97 ; J7.2 10.16,39.89 ; J1.3 19.7,3.65 ; J1.3 18.79,2.73 ; J1.3 20.62,2.73 ; J1.3 19.7,1.82 ; JMP5.6 57.73,4.22 ; JMP5.6 58.64,3.3 ; JMP5.6 57.73,2.39 ; JMP5.6 56.81,3.3 ; 28.67,11.81 28.67,12.73 ; 28.67,11.81 28.67,10.9 ; 28.67,11.81 27.76,11.81 ; 28.67,11.81 29.59,11.81 ; 37.18,1.92 J3.3 ; J3.3 37.18,3.75 ; J3.3 36.27,2.84 ; J3.3 38.1,2.84 ; P1.2 8.18,25.83 ; P1.2 6.85,26.61 ; P1.2 5.52,25.83
  BOTTOM w0.102: U6.B5 U6.A5 v2(29.13,43.36) ; U6.L4 v2(29.63,37.48) ; U6.A1 v2(31.75,43.56) ; U6.L1 v2(31.72,37.34)
  BOTTOM w0.241: R27.2 v1(44.92,51.24) ; C21.2 39.25,24.67 v3(39.88,24.05) 40.06,24.23 C24.2 ; P1.3 1.8,26.66 ; P1.3 3.28,25.83 ; P1.3 1.8,25 ; v1(20.34,32.9) C29.2 C28.2 v1(21.51,32.81) ; R10.2 v1(71.6,18.54) ; 6.85,26.61 P1.2 5.52,25.83 ; 5.52,17.42 P1.5 6.25,16.41 ; R13.2 v1(44.23,13.58) ; P1.4 3.28,17.19 ; P1.4 1.8,18.02 ; P1.4 1.8,16.36 ; P2.10 68,44.2 ; P2.10 65.92,42.12 ; P2.10 70.08,42.12 ; P2.10 68,40.03 ; C23.2 v2(42.56,19.08) ; 5.52,17.19 P1.6 ; P1.6 6.85,16.41 ; P1.6 8.18,17.19 ; v2(11.53,23.06) U5.3 U5.8 ; C25.2 38.75,21.23 v3(38.78,21.2) ; 6.25,26.61 P1.1 5.52,25.61 ; R36.2 v1(48.6,4.73) ; R32.2 v1(68.11,4.87) ; R64.2 v1(18.54,53.62) ; R31.2 v1(59.13,4.73) ; v3(40.98,21.2) 41.38,20.8 C22.2 ; U3.8 U3.3 v2(11.61,20.02) ; R23.2 v1(29.62,13.26) ; C26.2 39.72,19.69 v3(39.88,19.85) ; R9.2 v1(71.6,19.66) ; R21.2 v1(16.25,13.48) ; R26.2 v1(46.3,40.32) ; C42.2 v1(48.67,53.47) ; R63.2 v1(18.54,54.89) ; U7.4 v1(24.41,46.28) ; R62.2 v1(18.54,56.16)
  vias: v1(3.62,16.42) v1(3.73,26.57) v1(4.32,16.42) v1(4.43,26.57) v1(5.04,16.41) v1(5.15,26.56) v1(23.32,43.83) v1(38.71,40.69) v1(38.71,40.06) v1(38.71,39.42) v1(38.71,38.79) v1(38.71,38.15) v1(53.19,42.29) v1(53.16,41.55) v1(53.44,40.82) v1(53.87,41.53) v1(54.15,40.82) v1(72.65,40.19) v1(72.65,39.56) v1(72.65,38.92) v1(73.29,40.19) v1(73.29,39.56) v1(73.29,38.92) v1(73.92,40.19) v1(73.92,39.56) v1(73.92,38.92) v1(75.11,40.15) v1(75.11,39.51) v1(75.11,38.88) v1(75.74,40.15) v1(75.74,39.51) v1(75.74,38.88) v1(76.38,40.15) v1(76.38,39.51) v1(76.38,38.88) v2(27.21,39.94) v2(27.23,39.07) v2(27.25,41.44) v2(27.26,40.94) v2(27.25,40.44) v2(27.63,42.05) v2(27.64,39.07) v2(34.95,37.87) v2(40.86,16) v2(41.88,34.21) v2(41.99,32.92) v2(42,16.05) v2(42,13.63) v2(43.3,13.63) v3(38.78,22.7) v3(39.88,22.7) v3(39.88,21.2) v3(40.98,22.7)
VBUS:
  vias: v1(5.52,33.15) v1(6.27,33.15) v1(7,33.15) v1(7.67,33.16) v1(63.73,37.51) v1(63.73,36.88) v1(64.36,37.51) v1(64.36,36.88) v1(65,37.51) v1(65,36.88) v2(25.37,38.84) v2(25.37,38.51) v2(25.7,39.01) v2(25.7,38.66) v2(26.39,43.64) v2(26.62,43.38) v2(26.85,43.64)
VBUS_DS: length 0.4
  BOTTOM w0.254: U6.H10 26.69,39.5 v2(27.03,39.5)
  vias: v1(66.36,36.78) v1(67.05,36.79) v1(67.71,36.77) v2(25.67,42.59) v2(25.67,42.27) v2(25.68,41.93)
VDDIO: length 3.3
  BOTTOM w0.102: v2(32.27,43.25) 32.01,43.25 31.2,42.44 U6.B1
  BOTTOM w0.508: v1(51.47,32.06) R86.1 R85.2
  vias: v1(33.84,32.3) v1(33.87,31.53)
3P3VCC: length 4.8
  TOP w0.241: R4.1 64.2,16.22 v1(64.64,15.77) P3.20
  BOTTOM w0.241: v1(41.1,13.61) 41.1,13.61 R12.2 ; R1.1 64.13,15.26 v1(64.64,15.77)
  vias: v1(58.17,39.75) v1(58.19,39.17) v1(58.19,38.58)
1064_VCC: length 20.1
  TOP w0.241: U1.28 v2(41.73,19.05) ; U1.20 v2(37.98,19.15) ; U1.6 v2(39.28,25.56)
  BOTTOM w0.241: R25.2 45.91,54.39 46.53,53.78 v1(46.53,50.72) ; v1(17.89,16.06) 16.99,16.06 R19.2 ; R24.2 v1(46.39,42.81) ; R20.2 27.65,18.72 27.72,18.59 27.63,18.29 v1(27.69,18.19) ; C21.1 39.27,25.57 v2(39.28,25.56) 39.31,25.6 C24.1 ; R30.2 v1(68.09,7.31) ; C26.1 38.08,19.05 v2(37.98,19.15) 37.98,19.55 37.87,19.66 C25.1 ; R34.2 49.49,7.33 49.53,7.36 v1(50.24,7.36) ; R35.2 v1(10.54,5.97) ; R22.2 17.75,9.64 v1(17.72,9.66) ; C22.1 41.71,19.07 v2(41.73,19.05) 41.66,18.98 C23.1 ; R29.2 v1(60.74,7.27) ; R33.2 v1(34.41,8.93) ; R28.2 v1(27.03,5.83)
  vias: v1(58.01,31.56) v1(58.01,30.93) v1(58.01,30.29) v1(58.64,31.56) v1(58.64,30.93) v1(58.64,30.29) v1(59.28,31.56) v1(59.28,30.93) v1(59.28,30.29)
AUXN: length 14
  TOP w0.14: R6.2 53.25,16.18 54.44,16.18 R18.1 54.94,16.5 60.06,16.5 61.2,17.64 63.37,17.64 R4.2 64.23,17.26 64.23,17.27 P3.17
AUXP: length 14
  TOP w0.14: R8.2 53.23,17.07 54.45,17.07 R17.1 54.94,16.75 59.95,16.75 61.1,17.89 63.37,17.89 R14.1 64.23,18.28 64.24,18.27 P3.15
C_USB_BN: length 33.7
  TOP w0.14: P1.B7 v2(6.6,21.89)
  BOTTOM w0.102: U6.L7 28.1,37.91 28.1,37.85 28.12,37.83 28.12,36.83 27.95,36.66 27.95,36.46 27.99,36.43 27.99,36.35
  BOTTOM w0.14: 27.99,36.35 27.99,35.66 16.02,23.69 11.13,23.69 U5.2 U5.9 10.11,23.69 9.68,23.69 9.14,24.24 8.77,24.24 8.69,24.16 8.69,24.03 8.62,23.95 8.51,23.95 8.43,24.03 8.43,24.16 8.35,24.24 8.24,24.24 8.16,24.16 8.16,24.03 8.08,23.95 7.97,23.95 7.89,24.03 7.89,24.16 7.82,24.24 7.71,24.24 7.63,24.16 7.63,24.03 7.55,23.95 7.44,23.95 7.36,24.03 7.36,24.16 7.28,24.24 6.37,24.24 6.22,24.08 6.22,22.28 v2(6.6,21.89)
C_USB_BP: length 33.7
  TOP w0.14: P1.B6 v2(6.6,21.39)
  BOTTOM w0.102: U6.K7 28.13,38.35 27.88,38.11 27.88,37.76 27.9,37.74 27.9,36.92 27.74,36.75 27.74,36.35
  BOTTOM w0.14: 27.74,36.35 27.74,35.76 15.91,23.94 11.13,23.94 U5.1 U5.10 10.11,23.94 9.79,23.94 9.24,24.49 6.26,24.49 5.96,24.19 5.96,22.03 v2(6.6,21.39)
C_USB_TN: length 30.4
  TOP w0.14: v2(8.39,21.17) 8.3,21.25 7.67,21.25 P1.A7
  BOTTOM w0.102: U6.L6 28.63,36.95 28.61,36.93 28.61,36.38 28.63,36.36 28.63,36.35
  BOTTOM w0.14: 28.63,36.35 28.63,34.52 16.3,22.19 11.13,22.19 U5.5 U5.6 10.11,22.19 9.77,22.19 9.37,21.79 9.37,21.68 9.39,21.65 9.39,21.54 9.31,21.46 9.2,21.46 9.18,21.49 9.07,21.49 8.84,21.26 8.47,21.26 v2(8.39,21.17)
C_USB_TP: length 30.4
  TOP w0.14: P1.A6 7.68,21.51 8.29,21.51 v2(8.39,21.6)
  BOTTOM w0.102: 28.38,36.35 28.4,36.37 28.4,36.93 28.38,36.94 28.38,38.11 28.63,38.35 U6.K6
  BOTTOM w0.14: v2(8.39,21.6) 8.47,21.51 8.73,21.51 9.66,22.44 10.11,22.44 U5.7 U5.4 11.12,22.44 16.19,22.44 28.38,34.63 28.38,36.35
CC1: length 42
  TOP w0.241: v1(21.5,26.26) 21.5,26.89 16.87,31.52 14.83,31.52 J6.1 15.2,34.57 20.5,34.57 v1(21.51,35.58) ; v2(11.05,21.49) 10.65,21.49 10.65,21.49 9.28,21.49 8.64,22.14 P1.A5
  BOTTOM w0.241: U3.1 16.26,21.02 v1(21.5,26.26) ; U3.1 U3.10 ; U3.1 v2(11.05,21.49) ; C28.1 v1(21.51,35.58) 21.87,35.94 R37.2
CC2: length 46.4
  TOP w0.241: P1.B5 v2(6.6,20.89) ; v1(21.43,25.15) 17.82,28.76 15.05,28.76 J6.3 12.06,31.75 12.06,33.83 13.83,35.59 v1(20.34,35.59)
  BOTTOM w0.102: 24.46,36.78 R38.2
  BOTTOM w0.241: v2(6.6,20.89) 7.77,20.89 7.94,20.72 9.19,20.72 9.4,20.52 U3.9 U3.2 16.79,20.52 v1(21.43,25.15) ; 24.46,36.78 21.53,36.78 v1(20.34,35.59) C29.1
CONFIG1: length 3.6
  TOP w0.241: v1(68.5,19.66) 68.11,19.27 P3.13
  BOTTOM w0.241: v1(68.5,19.66) R9.1
CONFIG2: length 3.6
  TOP w0.241: v1(68.5,18.54) 68.28,18.77 P3.14
  BOTTOM w0.241: v1(68.5,18.54) R10.1
CTL0/SDA: length 98.6
  TOP w0.241: R41.2 v1(34.14,52.22) ; R5.2 35.31,14.5 38.61,17.8 v2(38.61,18.29) 38.88,18.56 U1.22
  L4_PWR w0.241: v1(34.14,52.22) 39.75,46.61 44.98,46.61 52.43,39.16 52.43,38.13 55.57,34.99 55.57,26.54 50.32,21.29 42.91,21.29 40.58,18.96 39.28,18.96 v2(38.61,18.29)
  BOTTOM w0.241: v2(38.61,18.29) 38.61,12.61 36.48,10.48 34.66,10.48 J2.2 ; v1(34.14,52.22) 38.35,56.44 38.35,60.25 JMP8.1
CTL1: length 89.1
  TOP w0.241: R43.2 v1(33.02,52.3) ; U1.23 39.28,18.38 v2(39.19,18.29)
  L4_PWR w0.241: v1(33.02,52.3) 33.81,53.09 34.57,53.09 40.31,47.35 45.13,47.35 53.03,39.44 53.03,38.43 56.37,35.1 56.37,26.22 49.29,19.14 43.48,19.14 42.63,18.29 v2(39.19,18.29)
  BOTTOM w0.241: J3.2 40.56,8.76 40.56,12.25 39.19,13.62 v2(39.19,18.29) ; JMP8.2 36.8,57.1 33.02,53.31 v1(33.02,52.3)
DBG_CTL1: length 30.2
  TOP w0.241: SW1.2 21.09,54.89 20.5,55.48 20.5,57.82 21.28,58.6 24.05,58.6 26.87,55.78 26.9,55.78 31.83,50.84 31.83,45.86 30.27,44.3 30.27,42.97 29.72,42.41 29.72,41.25 v2(30.03,40.94)
  BOTTOM w0.102: U6.E4 v2(30.03,40.94)
DBG_CTL2: length 20.6
  TOP w0.241: v2(29.13,41.85) 29.13,42.59 29.72,43.18 29.72,44.46 31.04,45.78 31.04,49.3 24.18,56.16 SW1.3
  BOTTOM w0.102: U6.D5 v2(29.13,41.85)
DP0N: length 13.3
  TOP w0.14: P3.3 64.84,24.27 64.47,24.64 53.49,24.64 C7.2
DP0P: length 13.3
  TOP w0.14: C5.2 53.49,24.89 64.47,24.89 64.84,25.27 P3.1
DP1N: length 13.4
  TOP w0.14: P3.6 64.84,22.77 64.47,23.14 60.25,23.14 60.02,22.91 53.49,22.91 C12.2
DP1P: length 13.4
  TOP w0.14: P3.4 64.84,23.77 64.47,23.39 60.14,23.39 59.92,23.17 53.49,23.17 C10.2
DP2N: length 13.5
  TOP w0.14: C16.2 53.43,21.13 53.44,21.13 59.99,21.13 60.51,21.64 64.47,21.64 64.84,21.27 P3.9
DP2P: length 13.5
  TOP w0.14: C14.2 53.54,21.38 59.89,21.38 60.4,21.89 64.47,21.89 64.84,22.27 P3.7
DP3N: length 13.6
  TOP w0.14: P3.12 64.84,19.77 64.47,20.14 61.29,20.14 60.61,19.46 53.49,19.46 C20.2
DP3P: length 13.6
  TOP w0.14: P3.10 64.84,20.77 64.47,20.39 61.19,20.39 60.5,19.71 53.49,19.71 C18.2
DPEQ0/A1: length 29.4
  TOP w0.241: U1.35 v2(42.69,22.15)
  BOTTOM w0.241: JMP6.3 59.29,10.36 56.12,10.36 44.33,22.15 v2(42.69,22.15)
DPEQ1: length 27.5
  TOP w0.241: v2(41.06,25.58) 40.88,25.4 U1.2
  BOTTOM w0.241: v2(41.06,25.58) 41.76,24.88 41.76,22 42.26,21.5 44.07,21.5 53.58,11.99 53.58,7.45 JMP5.3
EN: length 49.1
  TOP w0.241: U1.29 v2(42.73,19.75)
  BOTTOM w0.241: v2(42.73,19.75) 44.63,19.75 46.54,17.85 46.54,15.01 41.54,10.02 41.54,7.6 38.15,4.21 13.25,4.21 J4.2
EQ0: length 20.4
  TOP w0.241: v2(28.61,23.1) 29.01,23.1 29.26,23.35 U1.11
  BOTTOM w0.241: v2(28.61,23.1) 28.61,22.7 28.6,22.69 28.6,21.99 24.75,18.14 24.75,15.74 JMP2.3
EQ1: length 29.8
  TOP w0.241: U1.14 30.14,22.15 29.44,21.45 v2(26.34,21.45)
  BOTTOM w0.241: v2(26.34,21.45) 25.85,21.45 23.19,18.79 19.73,18.79 19.29,18.34 14.31,18.34 13.76,17.8 13.76,15.93 JMP1.3
FLIP/SCL: length 111
  TOP w0.241: R3.2 33.22,18.5 33.53,18.81 36.69,18.81 37.21,18.29 v2(38.02,18.29) 38.48,18.74 U1.21 ; R44.2 v1(19.94,42.11)
  L4_PWR w0.241: v2(38.02,18.29) 37.19,19.12 37.19,21.16 30.52,27.83 23.75,27.83 15.1,36.48 15.1,40.99 16.23,42.11 v1(19.94,42.11) 19.94,43.13 18.94,44.12 18.94,46.18 20.98,48.22 20.98,50.04 23.75,52.81 23.75,63.17 24.69,64.11 31.95,64.11 JMP8.3
  BOTTOM w0.241: v2(38.02,18.29) 38.02,12.82 36.45,11.25 30.79,11.25 29.27,9.73 26.31,9.73 21.85,5.27 J1.2
GPIO3: length 34.9
  L4_PWR w0.241: v2(24.16,38.99) 25.17,38 25.92,38 26.38,38.46 29.69,38.46 30.1,38.86 30.1,39.77 29.57,40.29 29.57,42.01 29.77,42.21 29.77,43.43 28.87,44.32 27.48,44.32 26.75,45.06 26.75,49.45 34.26,56.97 JMP8.4
  BOTTOM w0.102: 24.46,39.24 24.79,39.57 25.35,39.57 25.71,39.94 U6.G11
  BOTTOM w0.241: v2(24.16,38.99) 24.46,39.24
GPIO5: length 36.5
  TOP w0.241: R42.1 v1(19.99,39.98)
  L4_PWR w0.241: JMP8.6 30.45,60.53 30.45,62.89 30.07,63.27 25.4,63.27 24.36,62.23 24.36,52.45 21.72,49.81 21.72,47.82 19.48,45.59 19.48,44.57 20.62,43.43 20.62,40.61 v1(19.99,39.98)
GPIO6: length 29.1
  L4_PWR w0.241: v2(23.79,38.61) 23.5,38.89 23.5,39.31 23.94,39.74 23.94,44.44 25.23,45.73 25.23,51.09 27.91,53.77 27.91,60.53 JMP8.7
  BOTTOM w0.102: U6.G10 26.38,39.69 25.83,39.69 25.3,39.17 25.02,39.17 24.46,38.61
  BOTTOM w0.241: v2(23.79,38.61) 23.84,38.56 24.41,38.56 24.46,38.61
GPIO7: length 20.6
  L4_PWR w0.241: JMP8.8 29.18,53.9 25.93,50.65 25.93,43.48 26.69,42.72 27.64,42.72 28.13,42.24 v2(28.13,41.84)
  BOTTOM w0.102: U6.D7 v2(28.13,41.84)
GPIO8: length 28
  TOP w0.241: R46.2 v2(24.65,37.83)
  L4_PWR w0.241: v2(24.65,37.83) 23.52,37.83 23.08,38.27 23.08,39.73 23.35,40 23.35,41.97 22.5,42.81 22.5,45.25 23.55,46.29 23.55,50.55 25.17,52.17 25.17,60.33 JMP8.9
HPD: length 86.4
  TOP w0.241: R40.1 31.49,33.02 31.51,33.03 38.32,33.03 41.81,36.53 v1(47.7,36.53) 47.7,44.86 45.66,46.89 45.66,56.14 37.82,63.98 33.91,63.98 JMP8.5 ; P3.18 66.19,16.76 v1(64.67,16.76)
  BOTTOM w0.241: 49.03,35.2 v1(47.7,36.53) ; R2.2 63.89,17.54 v1(64.67,16.76)
  BOTTOM w0.254: R2.2 61.77,17.54 49.03,30.28 49.03,35.2
HPDIN: length 23.8
  TOP w0.241: v1(49.12,20.42) 44.73,20.42 44.2,20.95 U1.32
  BOTTOM w0.241: R1.2 62.53,15.99 62.53,16 R2.1 62.01,16.5 61.98,16.53 61.65,16.53 57.76,20.42 v1(49.12,20.42)
I2C_ADDR: length 32.6
  TOP w0.241: SW1.1 20.73,53.62 v1(20.7,53.59)
  BOTTOM w0.102: 32.89,40.51 32.64,40.51 32.56,40.44 U6.F1
  BOTTOM w0.241: 32.89,40.51 33.4,40.51 34.87,39.04 36.2,39.04 36.6,39.44 36.6,44.96 30.15,51.41 26.16,51.41 23.98,53.59 v1(20.7,53.59)
I2C_EN: length 23
  TOP w0.241: JMP7.3 42.19,5.84 v1(35.1,12.93) ; U1.17 v2(36.5,20.95)
  BOTTOM w0.241: v2(36.5,20.95) 36.5,20.55 36.68,20.37 36.68,16.02 35.98,15.32 35.98,13.81 v1(35.1,12.93)
I2C_IRQ1Z: length 6.4
  TOP w0.241: v2(35.66,44.63) R57.2
  BOTTOM w0.102: 32.89,42.41 32.75,42.41 32.61,42.27 31.88,42.27 31.55,41.94 U6.C1
  BOTTOM w0.241: 32.89,42.41 33.8,42.41 v2(35.66,44.63)
I2C_SCL: length 54.5
  TOP w0.241: R3.1 31.68,19.02 v1(32.13,19.47) ; v2(35.71,43.51) R58.2
  L4_PWR w0.241: v2(35.71,43.51) 34.57,42.37 32.36,42.37 31.22,41.22 31.22,39.15 32.19,38.18 32.19,36.01 30.3,34.12 v1(29.36,34.12) 20.55,34.12 16.63,38.04 v1(16.63,38.95)
  BOTTOM w0.102: U6.D2 30.87,41.68 31.67,41.68 32,42.01 32.7,42.01 32.75,42.06 32.89,42.06
  BOTTOM w0.241: R66.1 v1(16.63,38.95) ; 32.89,42.06 34.27,42.06 v2(35.71,43.51) ; v1(32.13,19.47) 32.13,25.7 29.36,28.48 v1(29.36,34.12)
I2C_SDA: length 61.6
  TOP w0.241: v2(35.69,42.42) R59.2 ; R5.1 v1(32.58,14.5)
  L4_PWR w0.241: v2(35.69,42.42) 35.03,41.76 32.43,41.76 31.78,41.11 31.78,39.09 32.54,38.33 32.54,38.31 32.73,38.12 32.73,35.8 30.47,33.54 v1(28.76,33.54) 20.35,33.54 15.75,38.14 15.75,40.76 v1(16.49,41.5)
  BOTTOM w0.102: U6.D1 31.78,41.44 32.05,41.71 32.76,41.71 32.81,41.66 32.89,41.66
  BOTTOM w0.241: v1(28.76,33.54) 28.76,27.89 31.51,25.14 31.51,18.52 32.58,17.45 v1(32.58,14.5) ; v2(35.69,42.42) 34.92,41.66 32.89,41.66 ; R70.1 v1(16.49,41.5)
LCO_1P8VA: length 1.3
  TOP w0.241: C32.1 30.83,38.25 v2(31.5,38.25)
  BOTTOM w0.102: v2(31.5,38.25) 31.31,38.44 U6.K1
LCO_1P8VD: length 15.8
  TOP w0.241: R87.2 v1(23.2,37.4) ; v2(30.91,43.56) 31.49,44.14 C31.1
  L4_PWR w0.241: v2(30.91,43.56) 30.91,41.73 30.69,41.51 30.69,38.6 30.12,38.03 29.01,38.03 27.96,36.98 23.62,36.98 v1(23.2,37.4)
  BOTTOM w0.102: U6.A2 30.63,43.27 v2(30.91,43.56)
LDO_3P3: length 15.6
  TOP w0.241: R58.1 v1(38.18,43.54) ; R57.1 v1(38.13,44.63) ; v1(22.71,50.09) 22.63,50.02 R74.1 21.14,50.02 21.07,49.95 C39.1 ; R59.1 v1(38.18,42.42) ; v2(32.72,39.8) 33.69,39.8 34.1,40.21 C30.1 ; R52.2 v1(20.66,37.28)
  BOTTOM w0.102: U6.G1 32.51,39.94 32.64,39.81 v2(32.72,39.8)
  BOTTOM w0.241: R72.1 v1(14.43,48.34) ; R68.1 v1(15.48,43.47) ; R73.2 v1(28.12,45.8) ; R71.1 v1(11.43,52.58) ; U7.8 v1(22.71,50.09) ; R67.1 v1(12.7,52.58)
  BOTTOM w0.508: R86.2 v1(50.44,32.08)
  vias: v1(20.19,44.75) v1(20.83,44.75) v1(21.44,44.75) v1(28.7,45.77)
LDO_BMC: length 2.1
  TOP w0.241: v2(32.33,41.1) 31.93,41.5 C33.1
  BOTTOM w0.102: U6.E1 32.07,40.94 32.23,41.1 v2(32.33,41.1)
RX1N: length 18.2
  TOP w0.14: P1.B10 v2(6.6,23.39) ; v2(8.52,22.59) 8.6,22.67 8.81,22.67 9.3,22.19 9.6,22.19 U2.5 U2.6 10.62,22.19 21.19,22.19 21.2,22.2 22.94,22.2 C11.1
  BOTTOM w0.14: v2(6.6,23.39) 6.73,23.51 6.95,23.51 7.78,22.68 8.43,22.68 v2(8.52,22.59)
RX1P: length 18.2
  TOP w0.14: v2(8.52,23.02) 8.62,22.93 8.92,22.93 9.4,22.44 9.6,22.44 U2.4 U2.7 10.62,22.44 21.08,22.44 21.1,22.46 22.94,22.46 C8.1 ; P1.B11 v2(6.6,23.89)
  BOTTOM w0.14: v2(6.6,23.89) 6.73,23.76 7.05,23.76 7.88,22.93 8.43,22.93 v2(8.52,23.02)
RX2N: length 16.8
  TOP w0.14: C13.1 22.94,20.73 13.17,20.73 13.01,20.89 10.67,20.89 U4.5 U4.6 9.65,20.89 9.31,20.89 8.88,20.46 8.88,20.15 8.24,19.51 7.67,19.51 P1.A10
RX2P: length 16.8
  TOP w0.14: C15.1 22.94,20.48 13.07,20.48 12.91,20.64 10.67,20.64 U4.4 U4.7 9.65,20.64 9.41,20.64 9.13,20.36 9.13,20.04 8.35,19.26 7.67,19.26 P1.A11
SBU1: length 67.5
  TOP w0.241: P1.A8 8.1,20.64 v2(8.42,20.31) ; v1(37.22,15.07) R7.1 37.95,14.55 37.94,14.55 R83.1
  L3_PWR w0.241: v2(8.42,20.31) 10.53,20.31 12.07,21.85 v1(12.07,24.91)
  BOTTOM w0.241: v1(37.22,15.07) 36.47,14.32 36.47,13.31 35.54,12.39 33.69,12.39 31.96,14.11 31.96,17.28 30.93,18.31 30.93,22.76 28.99,24.69 23.17,24.69 17.99,19.52 U3.4 U3.7 9.76,19.52 9.24,20.03 8.71,20.03 v2(8.42,20.31) ; R15.1 22.71,32.64 15.85,25.78 12.94,25.78 v1(12.07,24.91)
SBU2: length 71.1
  TOP w0.241: R84.1 37.94,12.38 37.95,12.39 R11.1 37.12,12.91 v1(37.1,12.92) ; P1.B8 v2(6.6,22.39)
  L3_PWR w0.241: v1(12.95,24.72) 12.6,24.37 12.6,21.72 10.28,19.41 v2(10.28,18.52)
  L4_PWR w0.241: v2(10.28,18.52) 8.28,18.52 7.62,19.18 7.62,21.98 7.21,22.39 v2(6.6,22.39)
  BOTTOM w0.241: v2(10.28,18.52) U3.6 U3.5 18.38,19.02 23.35,23.98 28.67,23.98 30.39,22.26 30.39,18.04 31.32,17.11 31.32,14.06 33.59,11.8 35.92,11.8 37.11,12.99 v1(37.1,12.92) ; v1(12.95,24.72) 13.46,25.23 16.05,25.23 23.9,33.08 R16.1
SPI_CLK: length 22.7
  TOP w0.241: v1(22.63,47.55) 29.67,47.55 v2(30.43,46.79)
  BOTTOM w0.102: U6.A3 30.13,43.61 30.76,44.25 30.76,44.7
  BOTTOM w0.241: v2(30.43,46.79) 30.43,46.3 30.76,45.97 30.76,44.7 ; v1(22.63,47.55) U7.6 15.4,47.55 14.45,46.6 R72.2 13.69,46.6 13.68,46.59 J7.7
SPI_HOLD#: length 2.7
  TOP w0.241: R74.2 22.57,48.98 v1(22.68,48.82)
  BOTTOM w0.241: U7.7 v1(22.68,48.82)
SPI_MISO: length 25.2
  BOTTOM w0.102: 29.63,44.7 U6.A4
  BOTTOM w0.241: 29.63,44.7 29.63,48 28.8,48.82 U7.2 24.41,48.82 23.39,47.8 23.39,46.28 22.45,45.34 15.69,45.34 14.44,44.09 R68.2 13.7,44.07 13.68,44.05 J7.5
SPI_MOSI: length 30.3
  TOP w0.241: v2(30.23,45.57) 30.23,46.18 29.49,46.91 23.27,46.91 v1(22.63,46.28)
  BOTTOM w0.102: U6.B4 29.88,42.69 29.88,44.36 30.23,44.7
  BOTTOM w0.241: v1(22.63,46.28) U7.5 15.82,46.28 14.88,45.34 11.41,45.34 J7.8 11.42,47.85 R71.2 ; v2(30.23,45.57) 30.23,44.7
SPI_SSZ: length 28
  BOTTOM w0.102: U6.B3 30.38,42.69 30.38,43.49 31.19,44.31 31.19,44.7
  BOTTOM w0.241: 31.19,44.7 31.19,47.73 28.83,50.09 U7.1 24.54,50.09 23.6,51.03 14.59,51.03 J7.9 R67.2
SPI_WP#: length 2.2
  BOTTOM w0.241: U7.3 27.38,47.55 27.39,47.56 R73.1
SSEQ0/A0: length 37.9
  TOP w0.241: v2(45.87,23.88) 45.34,23.35 U1.38
  BOTTOM w0.241: JMP4.3 38.56,51.18 38.56,47.37 40.82,45.11 40.82,38.02 46.64,32.2 46.64,24.65 v2(45.87,23.88)
SSEQ1: length 23.1
  TOP w0.241: v2(48.08,31.48) 45.66,29.06 43.49,29.06 40.48,26.05 U1.3
  BOTTOM w0.241: v2(48.08,31.48) 48.08,34.16 43.89,38.36 43.89,40.1 JMP3.3
SSRXN: length 17.8
  TOP w0.14: C2.2 52,39.83 52,43.26 54.55,45.81 63.63,45.81 P2.8
SSRXP: length 17.8
  TOP w0.14: C3.2 52.25,39.83 52.25,43.15 54.66,45.56 64.36,45.56 64.5,45.42 P2.9
SSTXN: length 24.5
  TOP w0.14: P2.5 63.63,51.81 55.52,51.81 48.97,45.26 48.97,39.83 C9.1
SSTXP: length 24.5
  TOP w0.14: C1.1 49.23,39.83 49.23,45.16 55.63,51.56 64.33,51.56 64.5,51.38 P2.6
SYS_PWR:
  vias: v1(16.43,43.36) v1(16.45,43.98) v1(17.09,43.98) v1(17.07,43.36) v1(17.7,43.98) v1(17.68,43.36) v1(46.76,48.03) v1(46.76,47.4) v1(47.37,48.03) v1(47.37,47.4) v1(47.98,48.03) v1(47.98,47.4) v1(60.69,57.44) v1(60.69,56.68) v1(60.69,55.92) v2(27.74,43.64) v2(27.92,43.31) v2(28.12,43.64)
TPS65986_3P3V: length 7.9
  TOP w0.241: 32.09,39.2 32.07,39.18 C37.1 31.14,39.37 C35.1 ; 32.09,39.2 v2(32.18,39.29) 32.76,38.72 C38.1 ; 32.09,39.2 C36.1
  TOP w0.508: C50.1 33.25,40.84 32.78,40.36 C35.1
  BOTTOM w0.102: U6.H1 31.86,39.44 32,39.29 v2(32.18,39.29)
  vias: v1(53.62,33.78) v1(53.62,33.15) v1(53.62,32.51) v1(54.25,33.78) v1(54.25,33.15) v1(54.25,32.51) v1(54.89,33.78) v1(54.89,33.15) v1(54.89,32.51)
TPS_AUX_N: length 44.1
  TOP w0.14: R18.2 v2(53.9,15.05)
  BOTTOM w0.102: U6.J2 30.71,38.94 30.95,39.18 31.69,39.18 32.05,38.81 32.85,38.81 32.87,38.83 32.89,38.83
  BOTTOM w0.14: v2(53.9,15.05) 53.9,16.36 54.04,16.5 54.9,16.5 55.6,17.2 55.6,18.54 54.94,19.2 49.31,19.2 43.01,25.5 43.01,34.16 39.78,37.39 34.7,37.39 33.26,38.83 32.89,38.83
TPS_AUX_P: length 44
  TOP w0.14: R17.2 v2(53.9,18.2)
  BOTTOM w0.102: U6.J1 31.15,38.96 31.6,38.96 31.97,38.6 32.85,38.6 32.87,38.58 32.89,38.58
  BOTTOM w0.14: 32.89,38.58 33.16,38.58 34.6,37.13 39.67,37.13 42.76,34.05 42.76,25.39 49.2,18.95 54.83,18.95 55.35,18.44 55.35,17.3 54.8,16.75 53.37,16.75 53.05,17.08 53.05,17.91 53.33,18.2 v2(53.9,18.2)
TPS_SBU1: length 7.6
  BOTTOM w0.102: 26.9,36.35 26.9,36.73 27.38,37.21 27.38,38.19 U6.K8
  BOTTOM w0.241: 26.9,36.35 25.91,35.36 22.9,35.36 22.71,35.16 R15.2
TPS_SBU2: length 5.9
  BOTTOM w0.102: U6.L8 27.63,36.97 27.33,36.68 27.33,36.35
  BOTTOM w0.241: R16.2 24.42,34.71 24.43,34.7 25.83,34.7 27.33,36.2 27.33,36.35
TX1N: length 16.3
  TOP w0.14: C6.1 22.94,23.93 21.76,23.93 21.52,23.69 10.62,23.69 U2.9 U2.2 9.6,23.69 8.61,23.69 8.18,23.26 7.67,23.26 P1.A3
TX1P: length 16.3
  TOP w0.14: P1.A2 7.67,23.51 8.08,23.51 8.5,23.94 9.6,23.94 U2.1 U2.10 10.62,23.94 21.41,23.94 21.66,24.18 22.94,24.18 C4.1
TX2N: length 17.9
  TOP w0.14: C17.1 22.94,19 21.29,19 20.9,19.39 10.67,19.39 U4.2 U4.9 9.74,19.48 v2(9.19,19.48) ; P1.B3 v2(6.6,19.89)
  BOTTOM w0.14: v2(6.6,19.89) 6.73,19.76 7.7,19.76 8.07,19.4 9.11,19.4 v2(9.19,19.48)
TX2P: length 17.9
  TOP w0.14: v2(6.6,19.39) 6.6,19.39 P1.B2 ; C19.1 22.94,18.75 21.18,18.75 20.79,19.14 10.67,19.14 U4.1 U4.10 9.74,19.05 v2(9.19,19.05)
  BOTTOM w0.14: v2(6.6,19.39) 6.73,19.51 7.6,19.51 7.97,19.14 9.11,19.14 v2(9.19,19.05)
USB_N: length 52.3
  TOP w0.14: P2.2 63.67,47.69 62.79,48.56 55.17,48.56 50.77,44.17 50.77,35.96 48.24,33.43 41.9,33.43 v2(41.81,33.34)
  BOTTOM w0.102: 29.08,36.35 29.08,36.45 29.1,36.47 29.1,36.82 28.88,37.03 28.88,37.45 28.88,37.6 28.88,37.61 28.88,37.7 28.88,38.11 29.13,38.35 U6.K5
  BOTTOM w0.14: v2(41.81,33.34) 41.72,33.43 31.37,33.43 29.08,35.72 29.08,36.35
USB_P: length 52.3
  TOP w0.14: P2.3 66,50.37 65.92,50.45 65.57,50.45 65.37,50.25 65.37,50.25 64.81,49.69 63.66,49.69 62.84,48.87 55.12,48.87 50.52,44.27 50.52,36.07 48.13,33.68 41.9,33.68 v2(41.81,33.77)
  BOTTOM w0.102: 29.33,36.35 29.33,36.37 29.31,36.39 29.31,36.91 29.09,37.12 29.09,37.45 29.1,37.59 29.1,37.6 29.11,37.69 29.11,37.92 U6.L5
  BOTTOM w0.14: 29.33,36.35 29.33,35.83 31.48,33.68 41.72,33.68 v2(41.81,33.77)
VOUT_3P3: length 3.6
  TOP w0.241: v2(33.04,39.26) 33.05,39.27 C34.1
  BOTTOM w0.102: U6.H2 30.88,39.69 32.29,39.69 32.51,39.47 32.69,39.47 32.89,39.27
  BOTTOM w0.241: 32.89,39.27 32.9,39.26 v2(33.04,39.26)
N51428: length 7.7
  TOP w0.241: P1.A4 6.92,22.64 6.67,22.89 v2(6.6,22.89) P1.B9 v2(5.41,22.89) ; P1.A9 6.98,20.14 6.72,20.4 6.61,20.4 v2(6.6,20.39) P1.B4 v2(5.43,20.39)
  BOTTOM w0.241: C46.1 4.83,19.79 v2(5.43,20.39) 5.02,20.79 C45.1 ; C47.1 4.97,23.32 v2(5.41,22.89) 4.84,22.32 C48.1
  vias: v1(5.28,30.34) v1(5.28,29.58) v1(5.28,28.81) v1(5.28,28.05)
N52896: length 14.3
  TOP w0.14: U1.9 37.89,24.06 37.12,24.06 37,24.18 24.15,24.18 C4.2
N52900: length 14.3
  TOP w0.14: C6.2 24.15,23.93 36.89,23.93 37.02,23.8 37.92,23.8 U1.10
N52912: length 14.9
  TOP w0.14: U1.18 37.94,20.51 30.74,20.51 29.96,19.73 25.75,19.73 25.03,19 24.15,19 C17.2
N52916: length 14.9
  TOP w0.14: U1.19 37.87,20.25 30.85,20.25 30.07,19.47 25.86,19.47 25.14,18.75 24.15,18.75 C19.2
N53113: length 21.9
  TOP w0.14: U1.5 39.75,24.92 39.75,27.25 44.93,32.42 49.44,32.42 52,34.98 52,38.62 C2.1
N53117: length 21.9
  TOP w0.14: C3.1 52.25,38.62 52.25,34.87 49.55,32.17 45.03,32.17 40.01,27.14 40.01,24.92 U1.4
